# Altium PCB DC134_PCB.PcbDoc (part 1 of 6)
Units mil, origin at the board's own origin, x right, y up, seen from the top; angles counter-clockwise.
Board outline 4000 x 2750 mil, 6 copper layers (L1_Top Layer, L2_GND1, L3_Signal, L4_Plane, L5_GND2, L6_Bottom Layer), stack 60.4 mil thick; 404 components, 244 nets, 1547 pads, 694 vias.
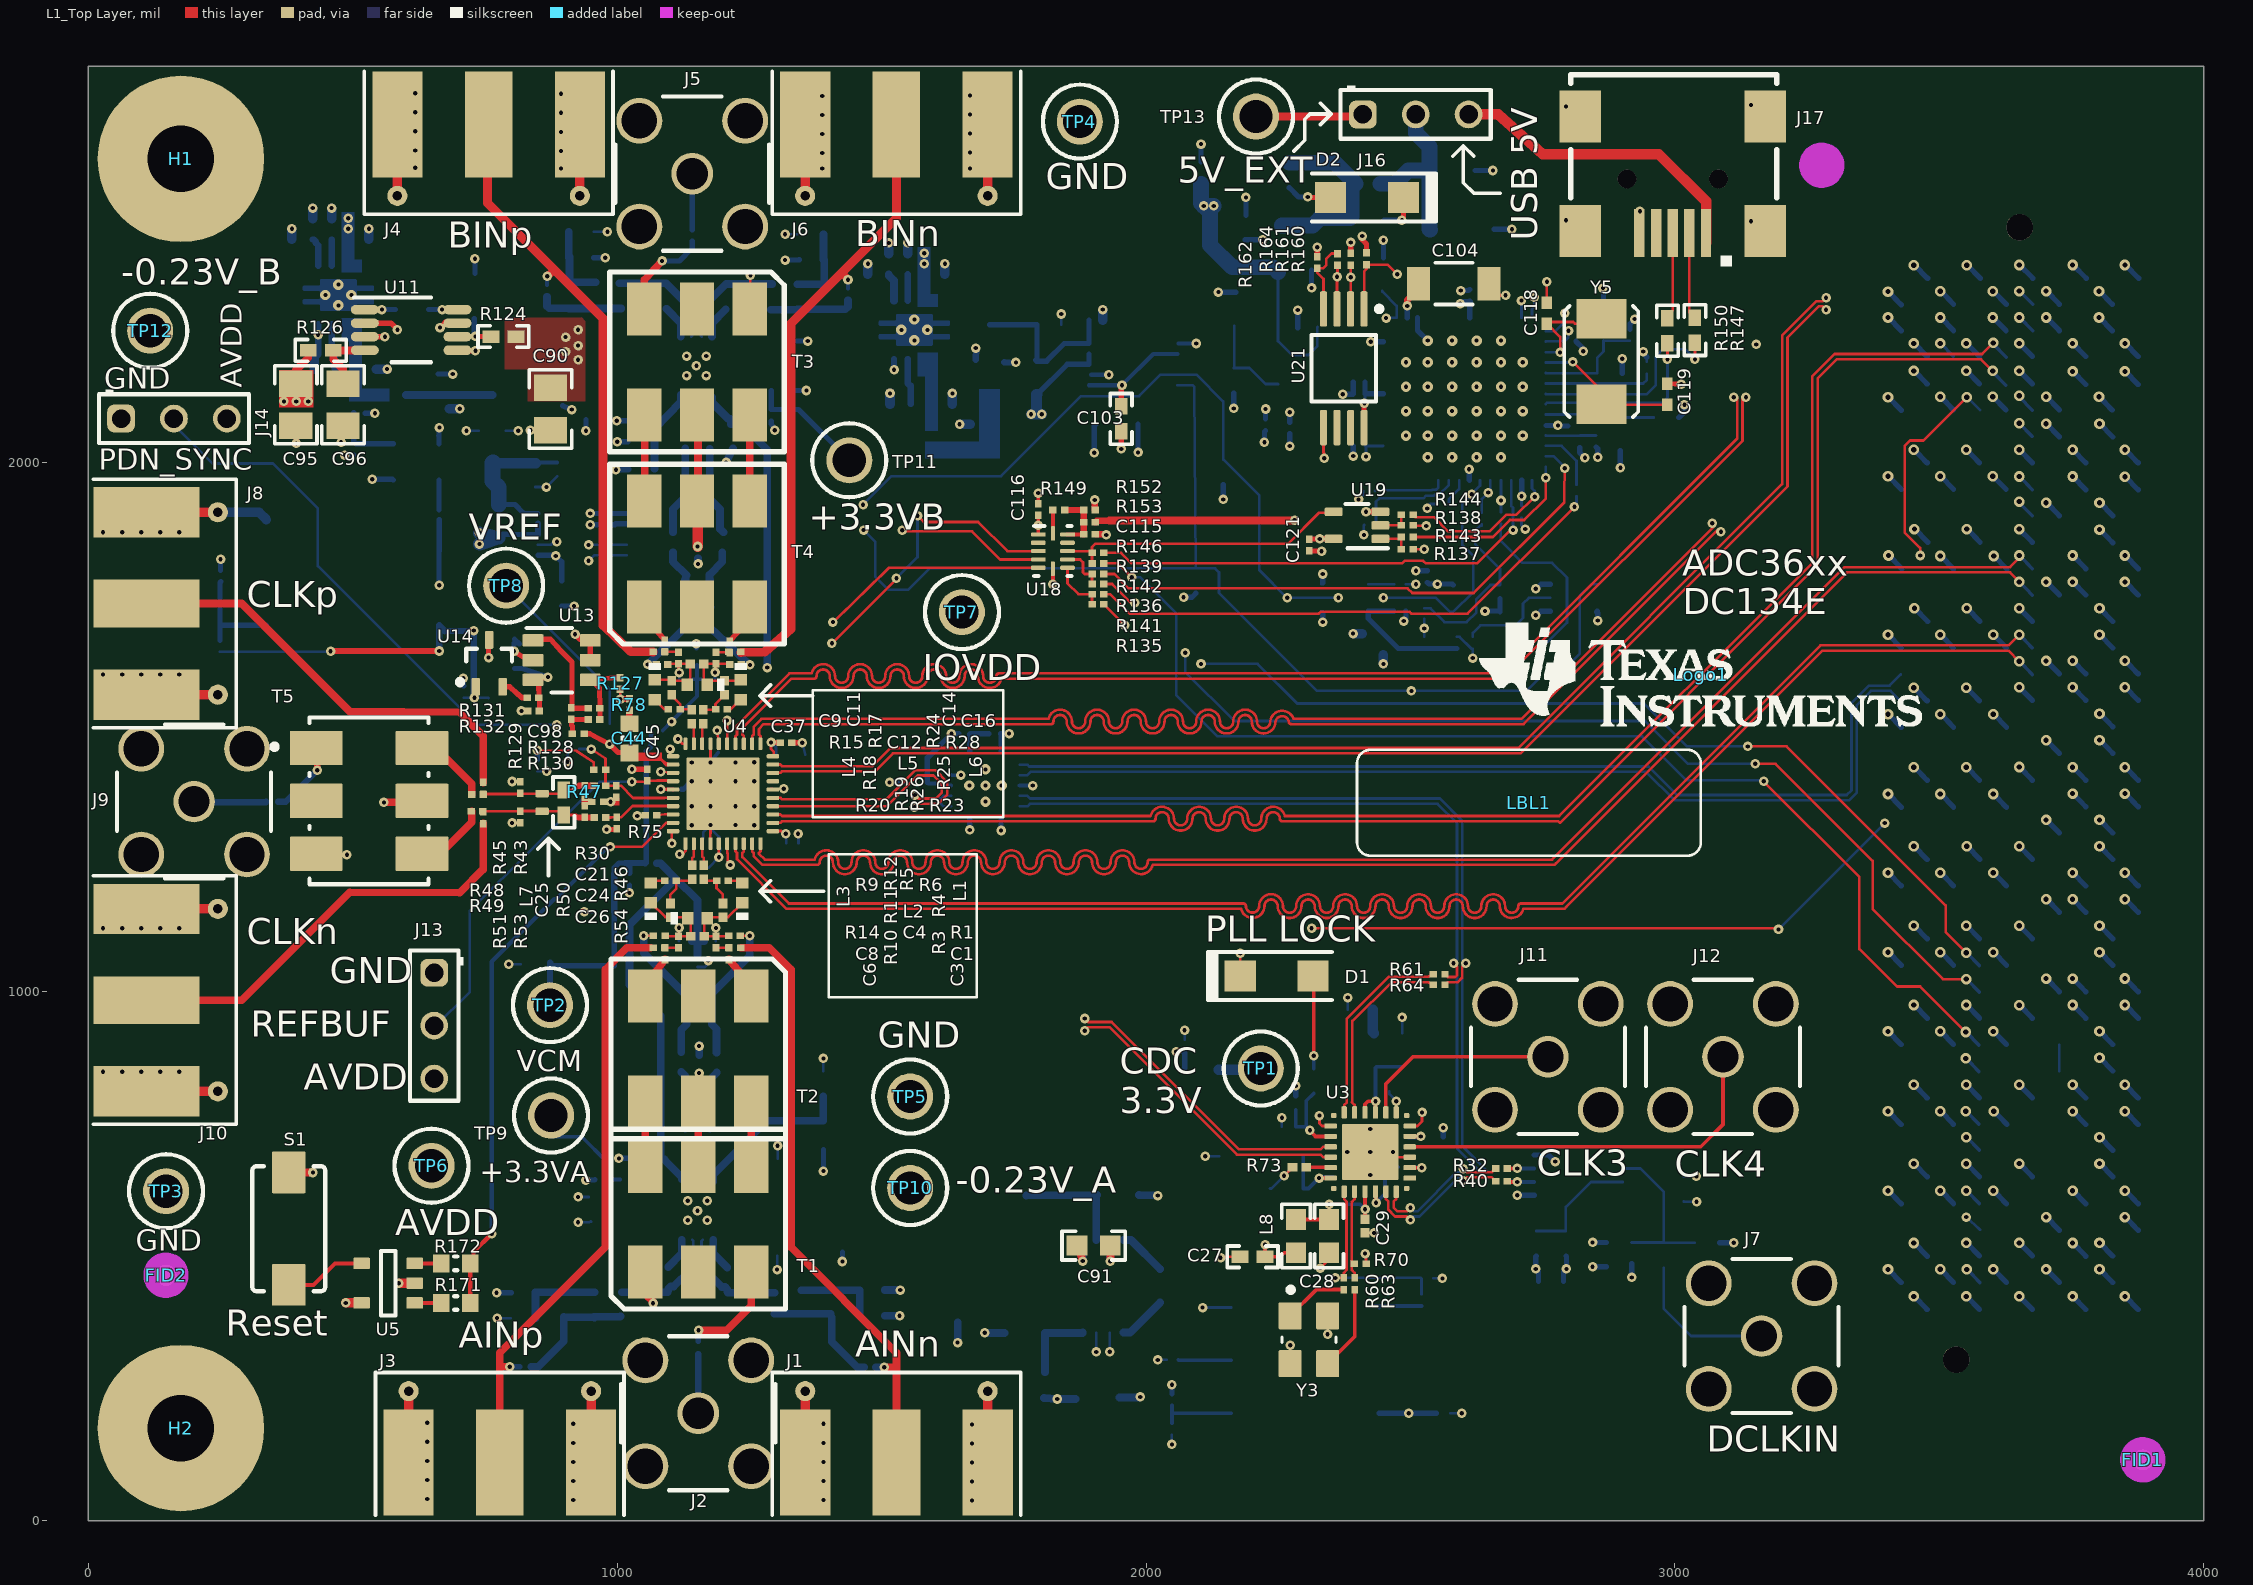
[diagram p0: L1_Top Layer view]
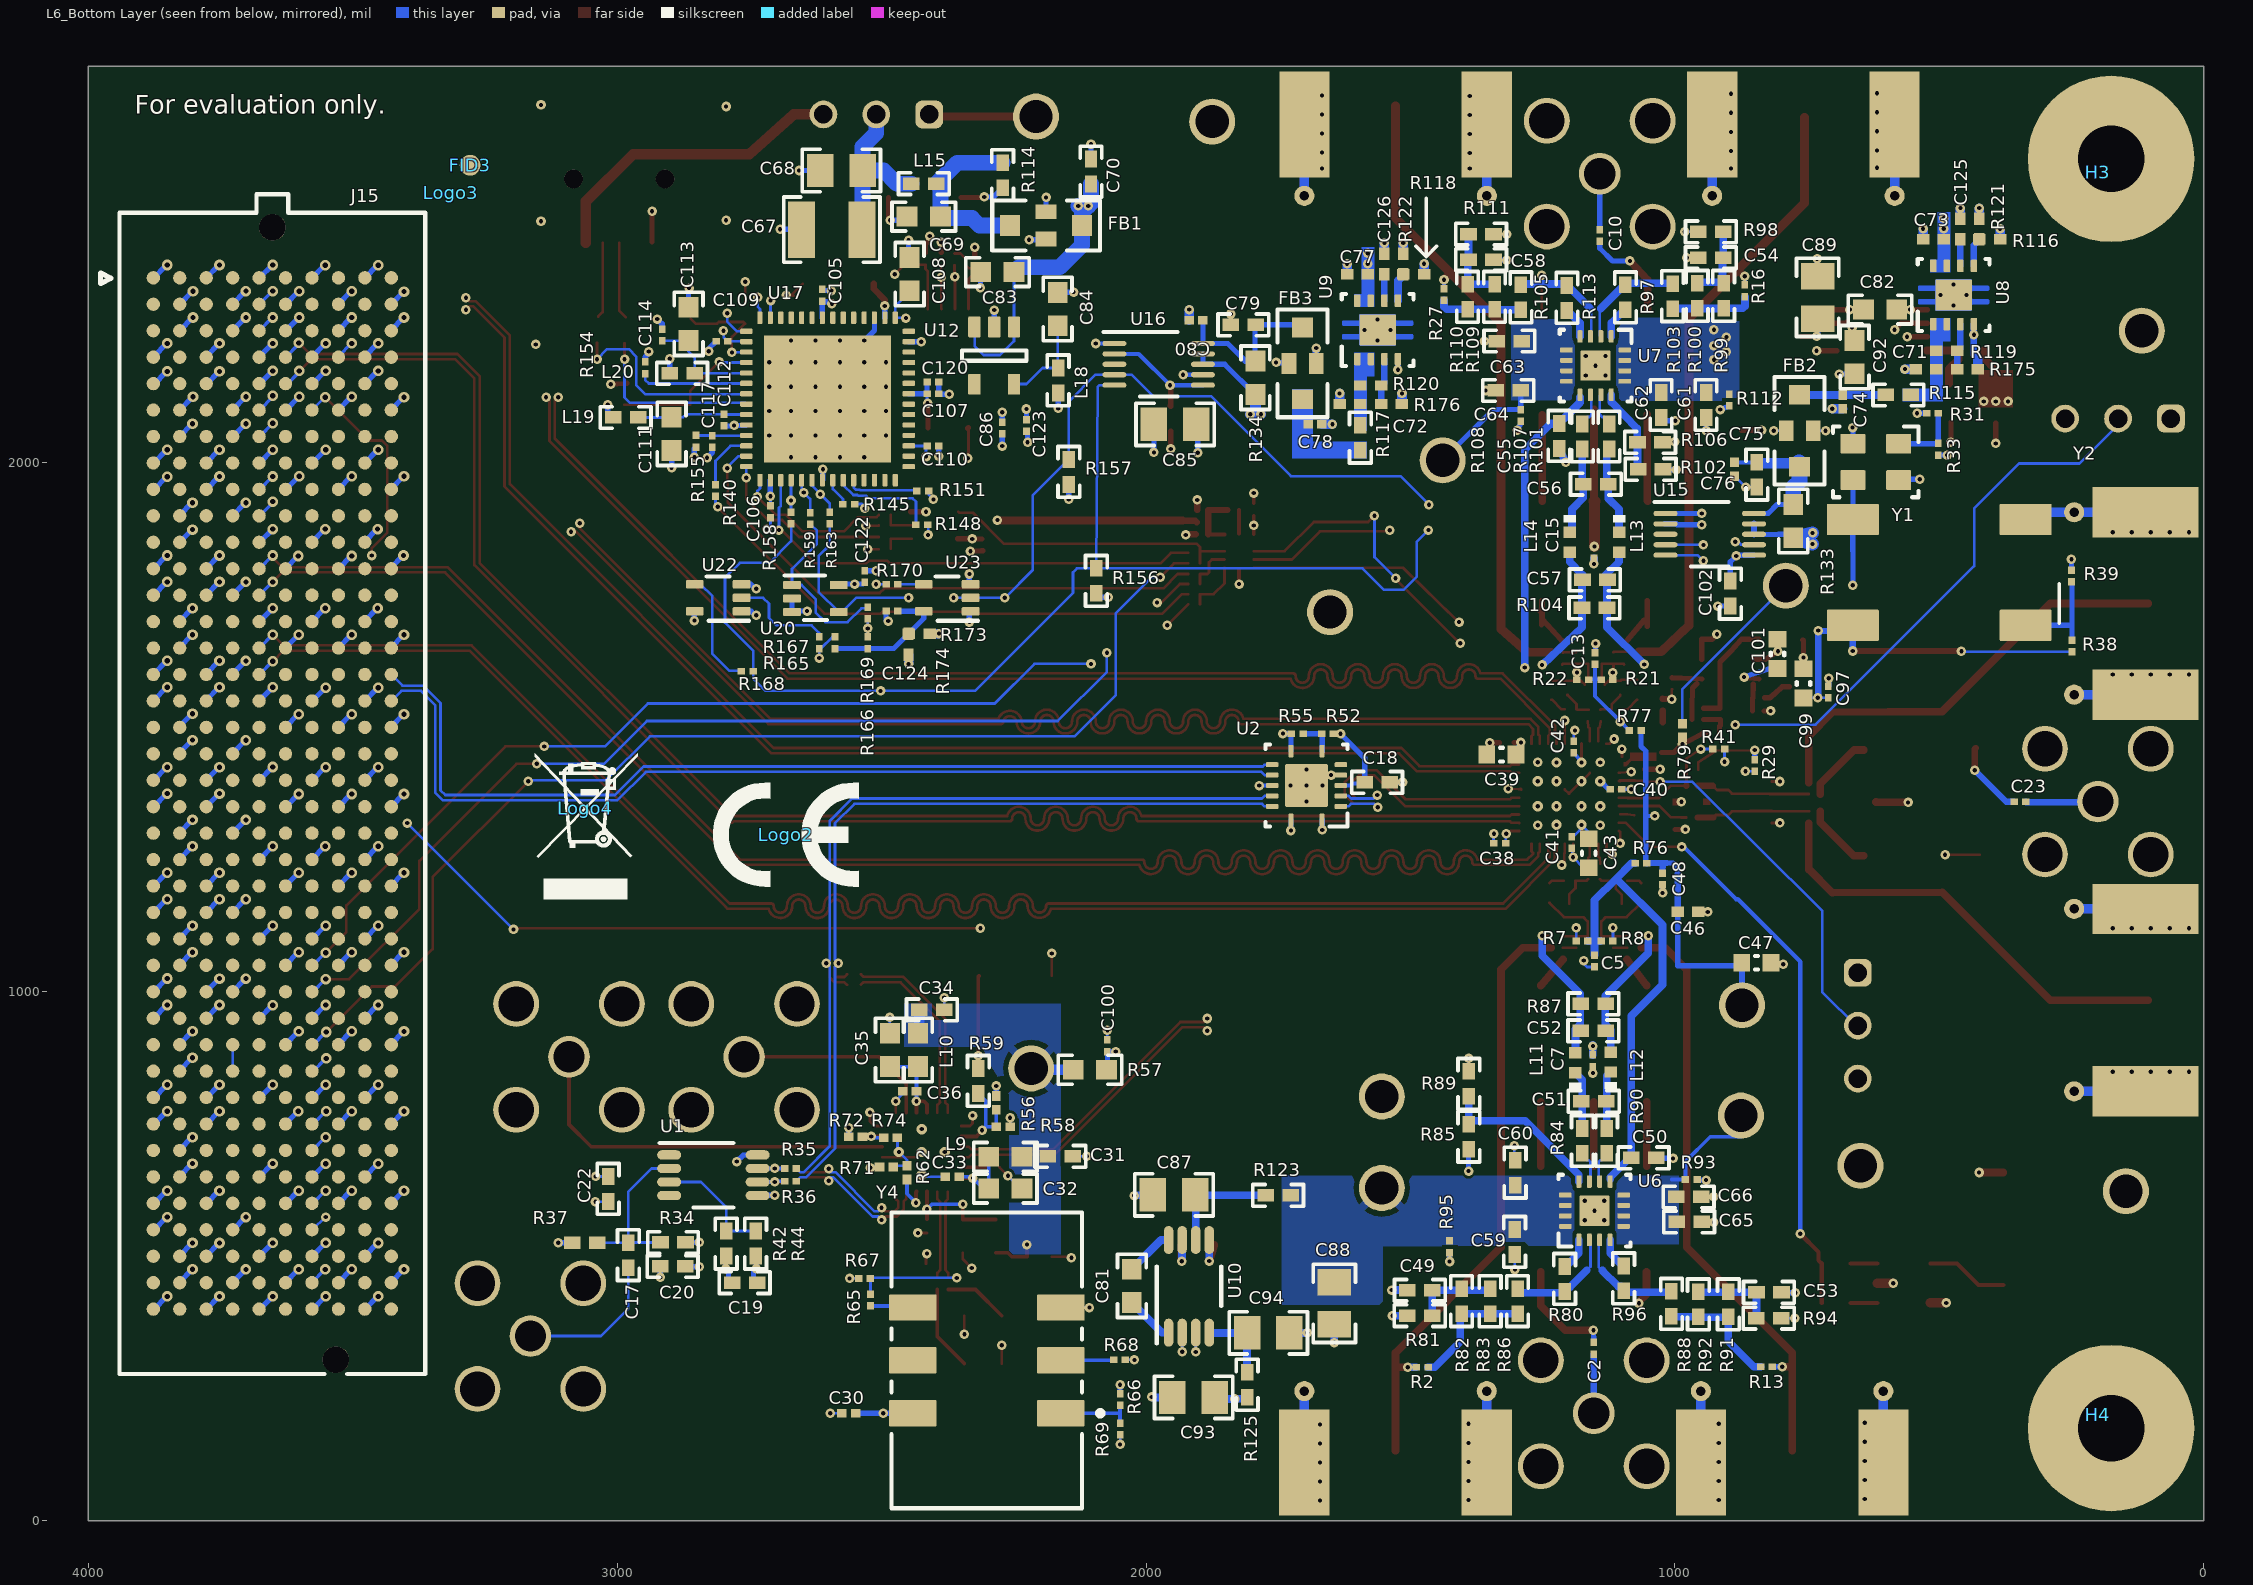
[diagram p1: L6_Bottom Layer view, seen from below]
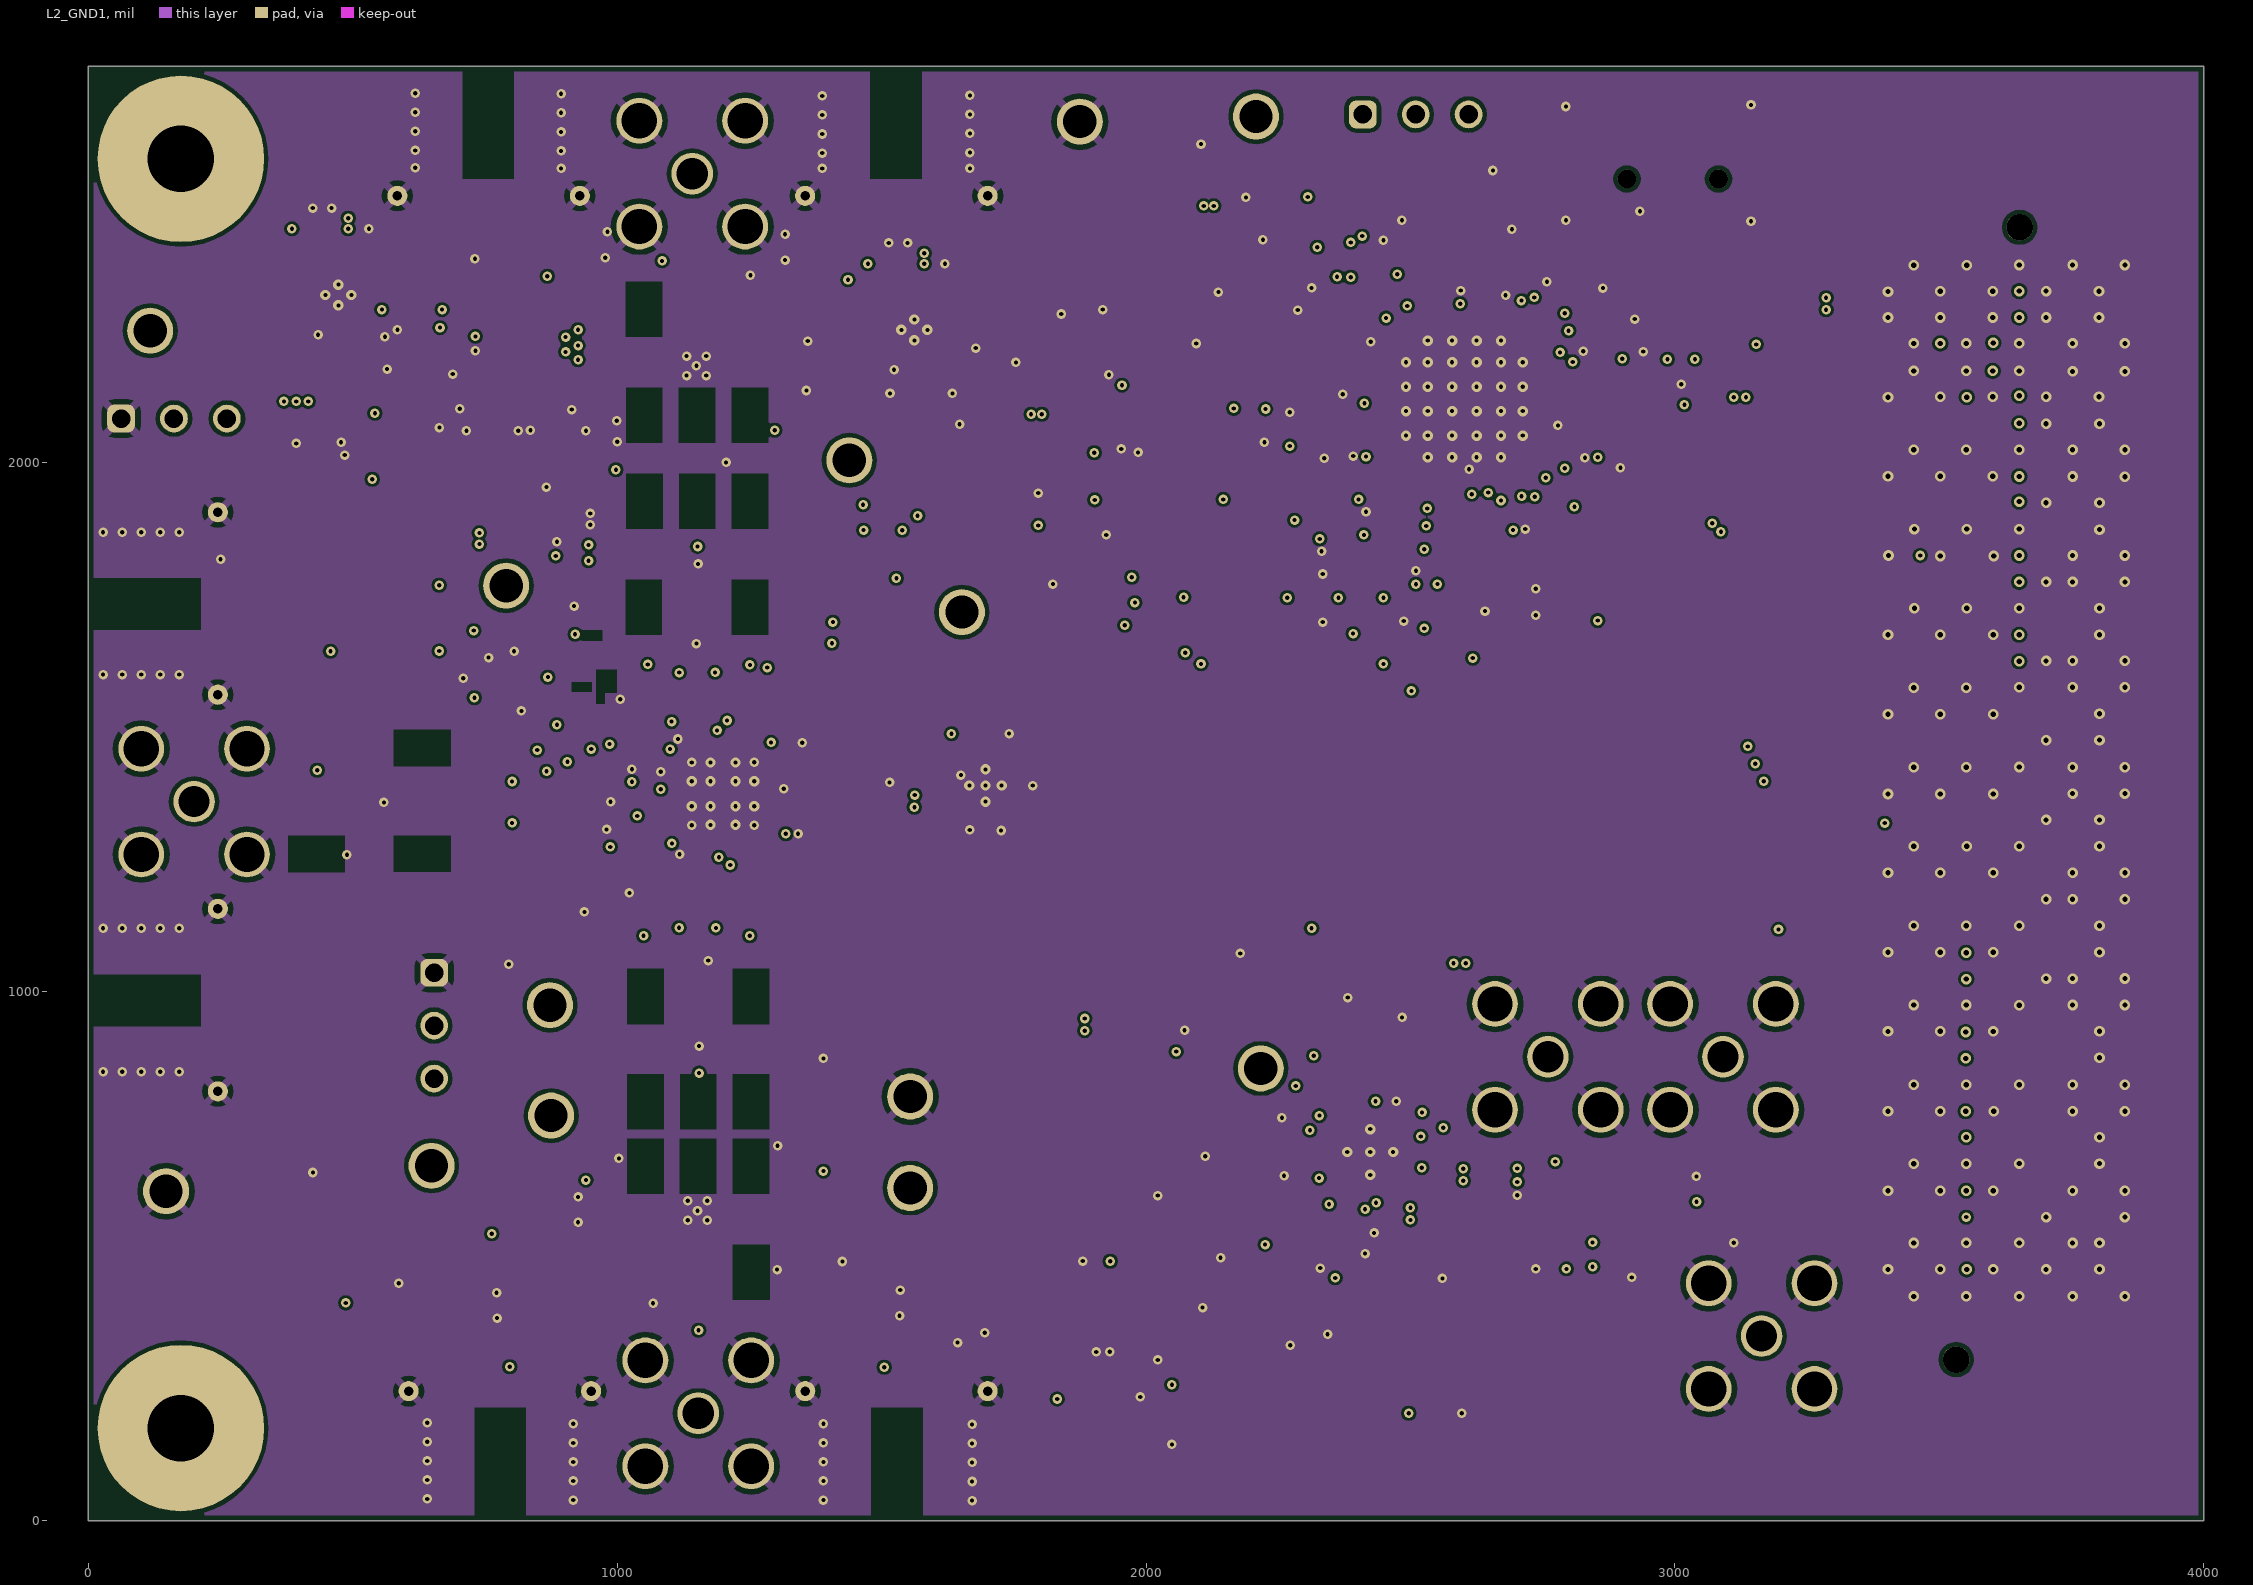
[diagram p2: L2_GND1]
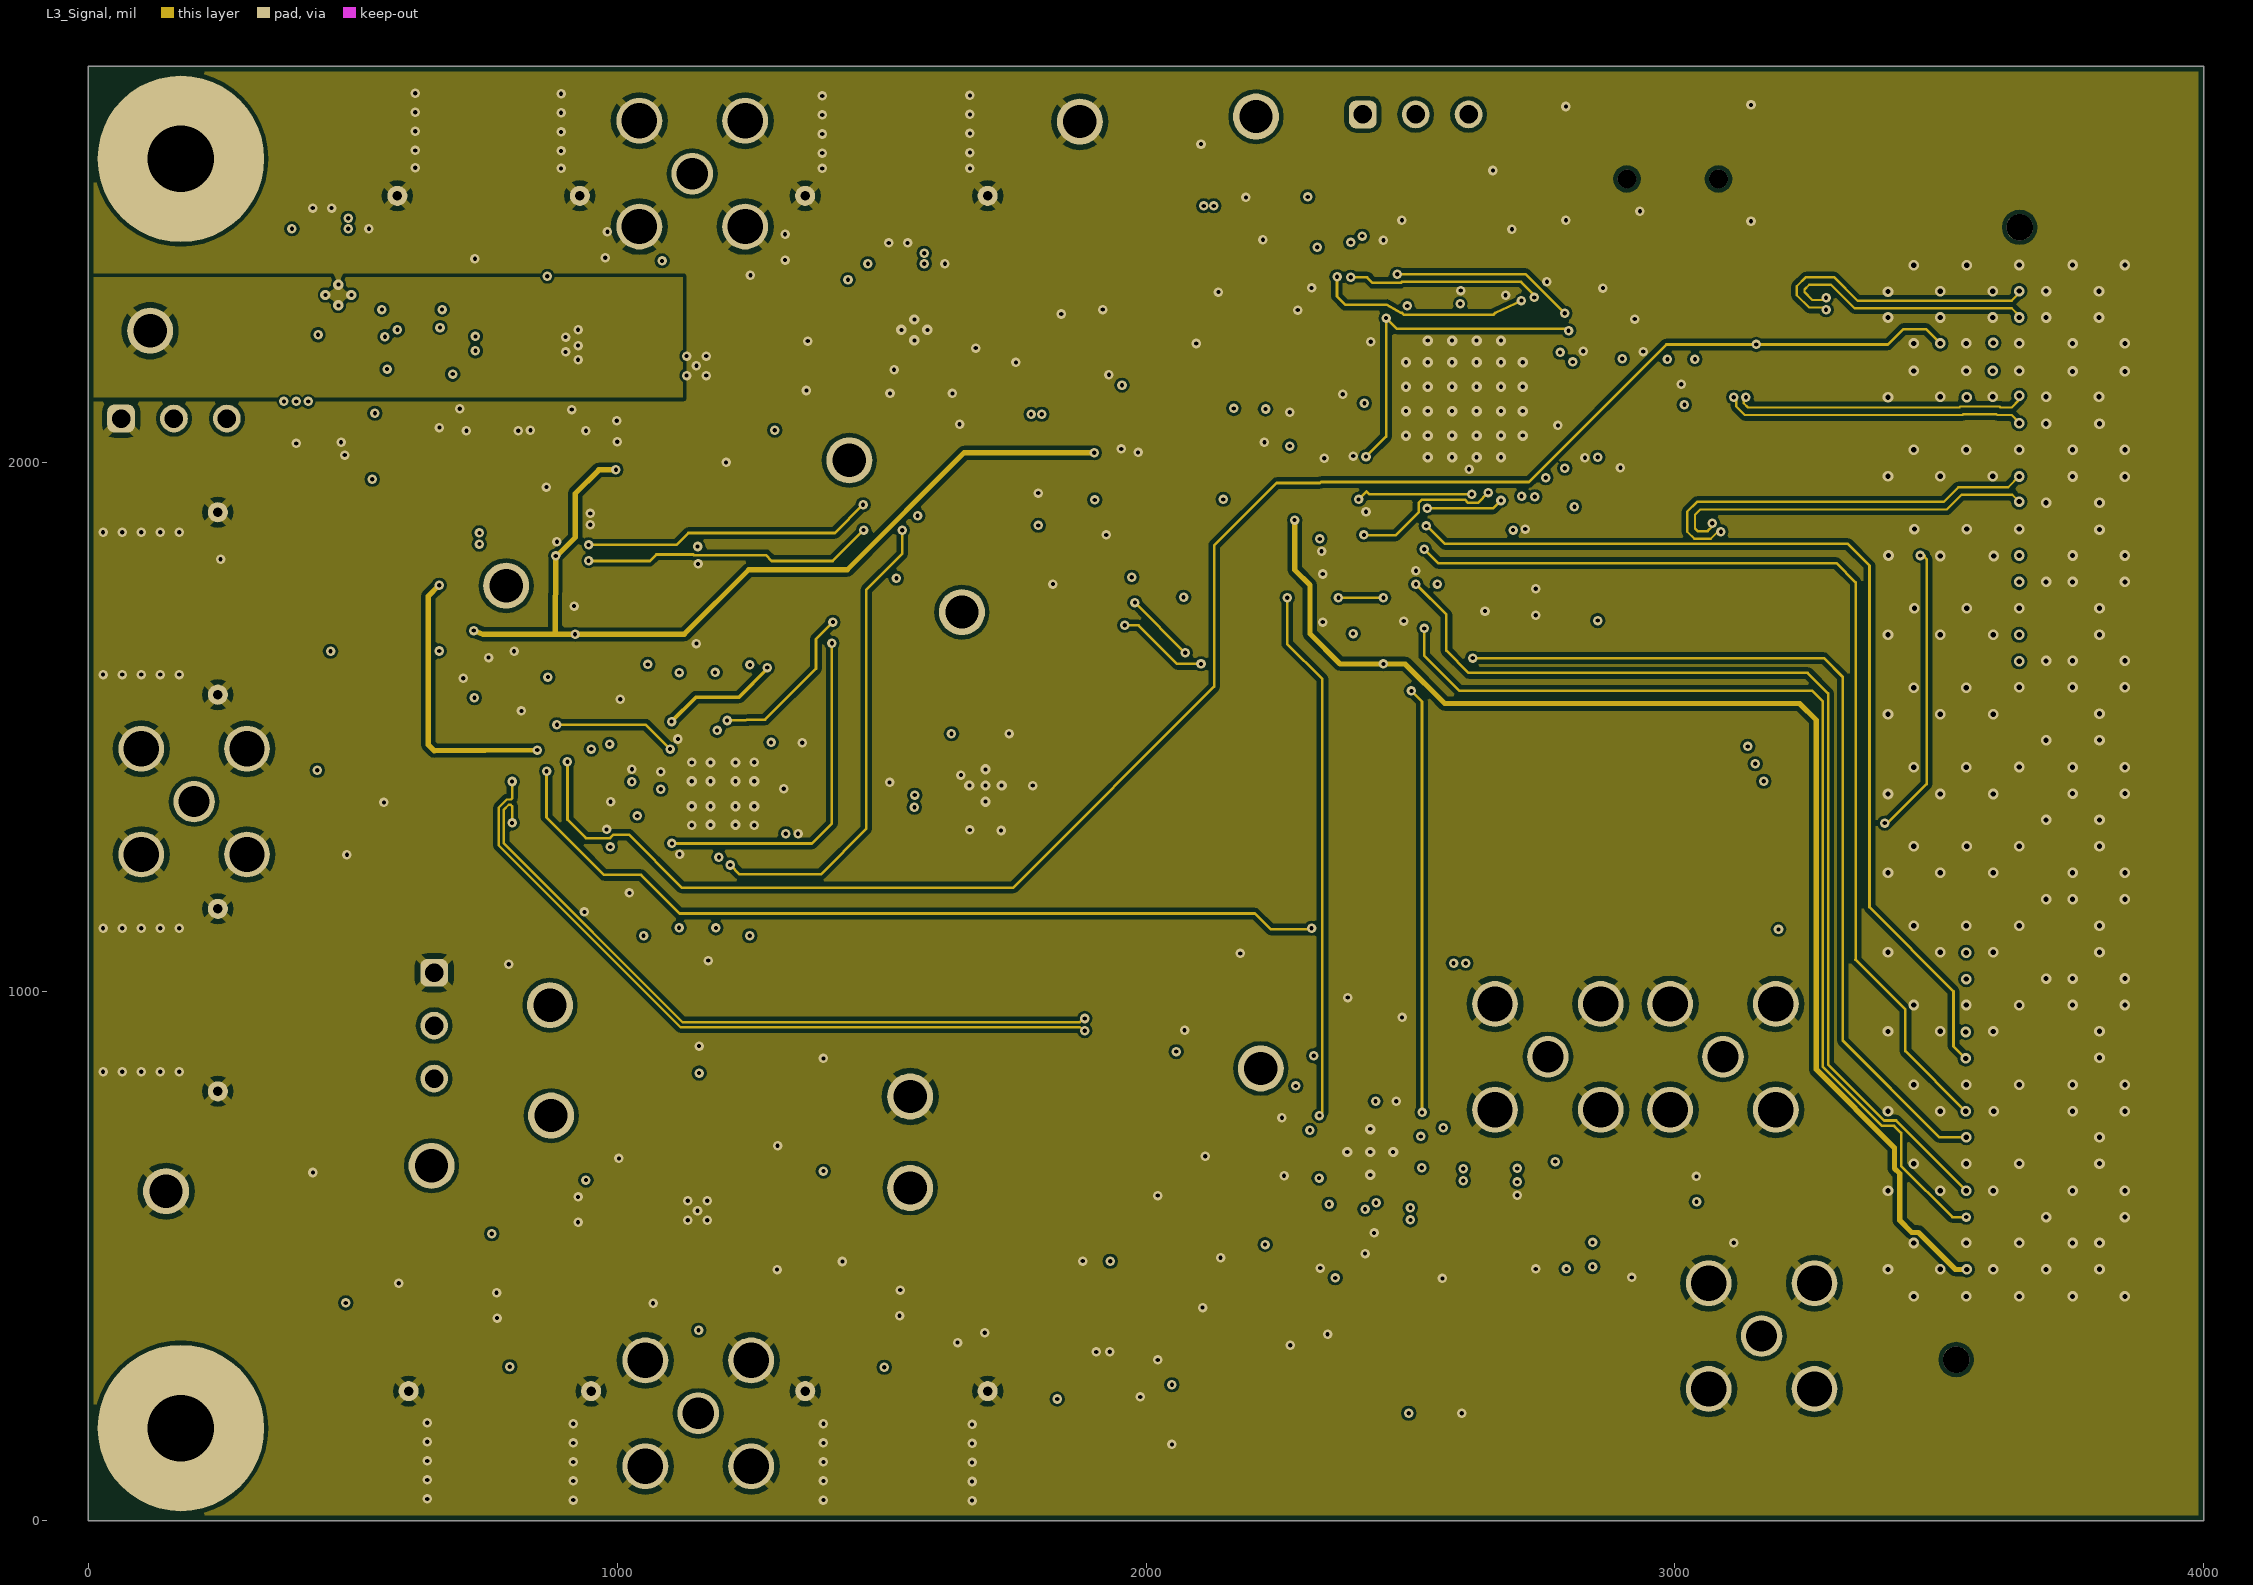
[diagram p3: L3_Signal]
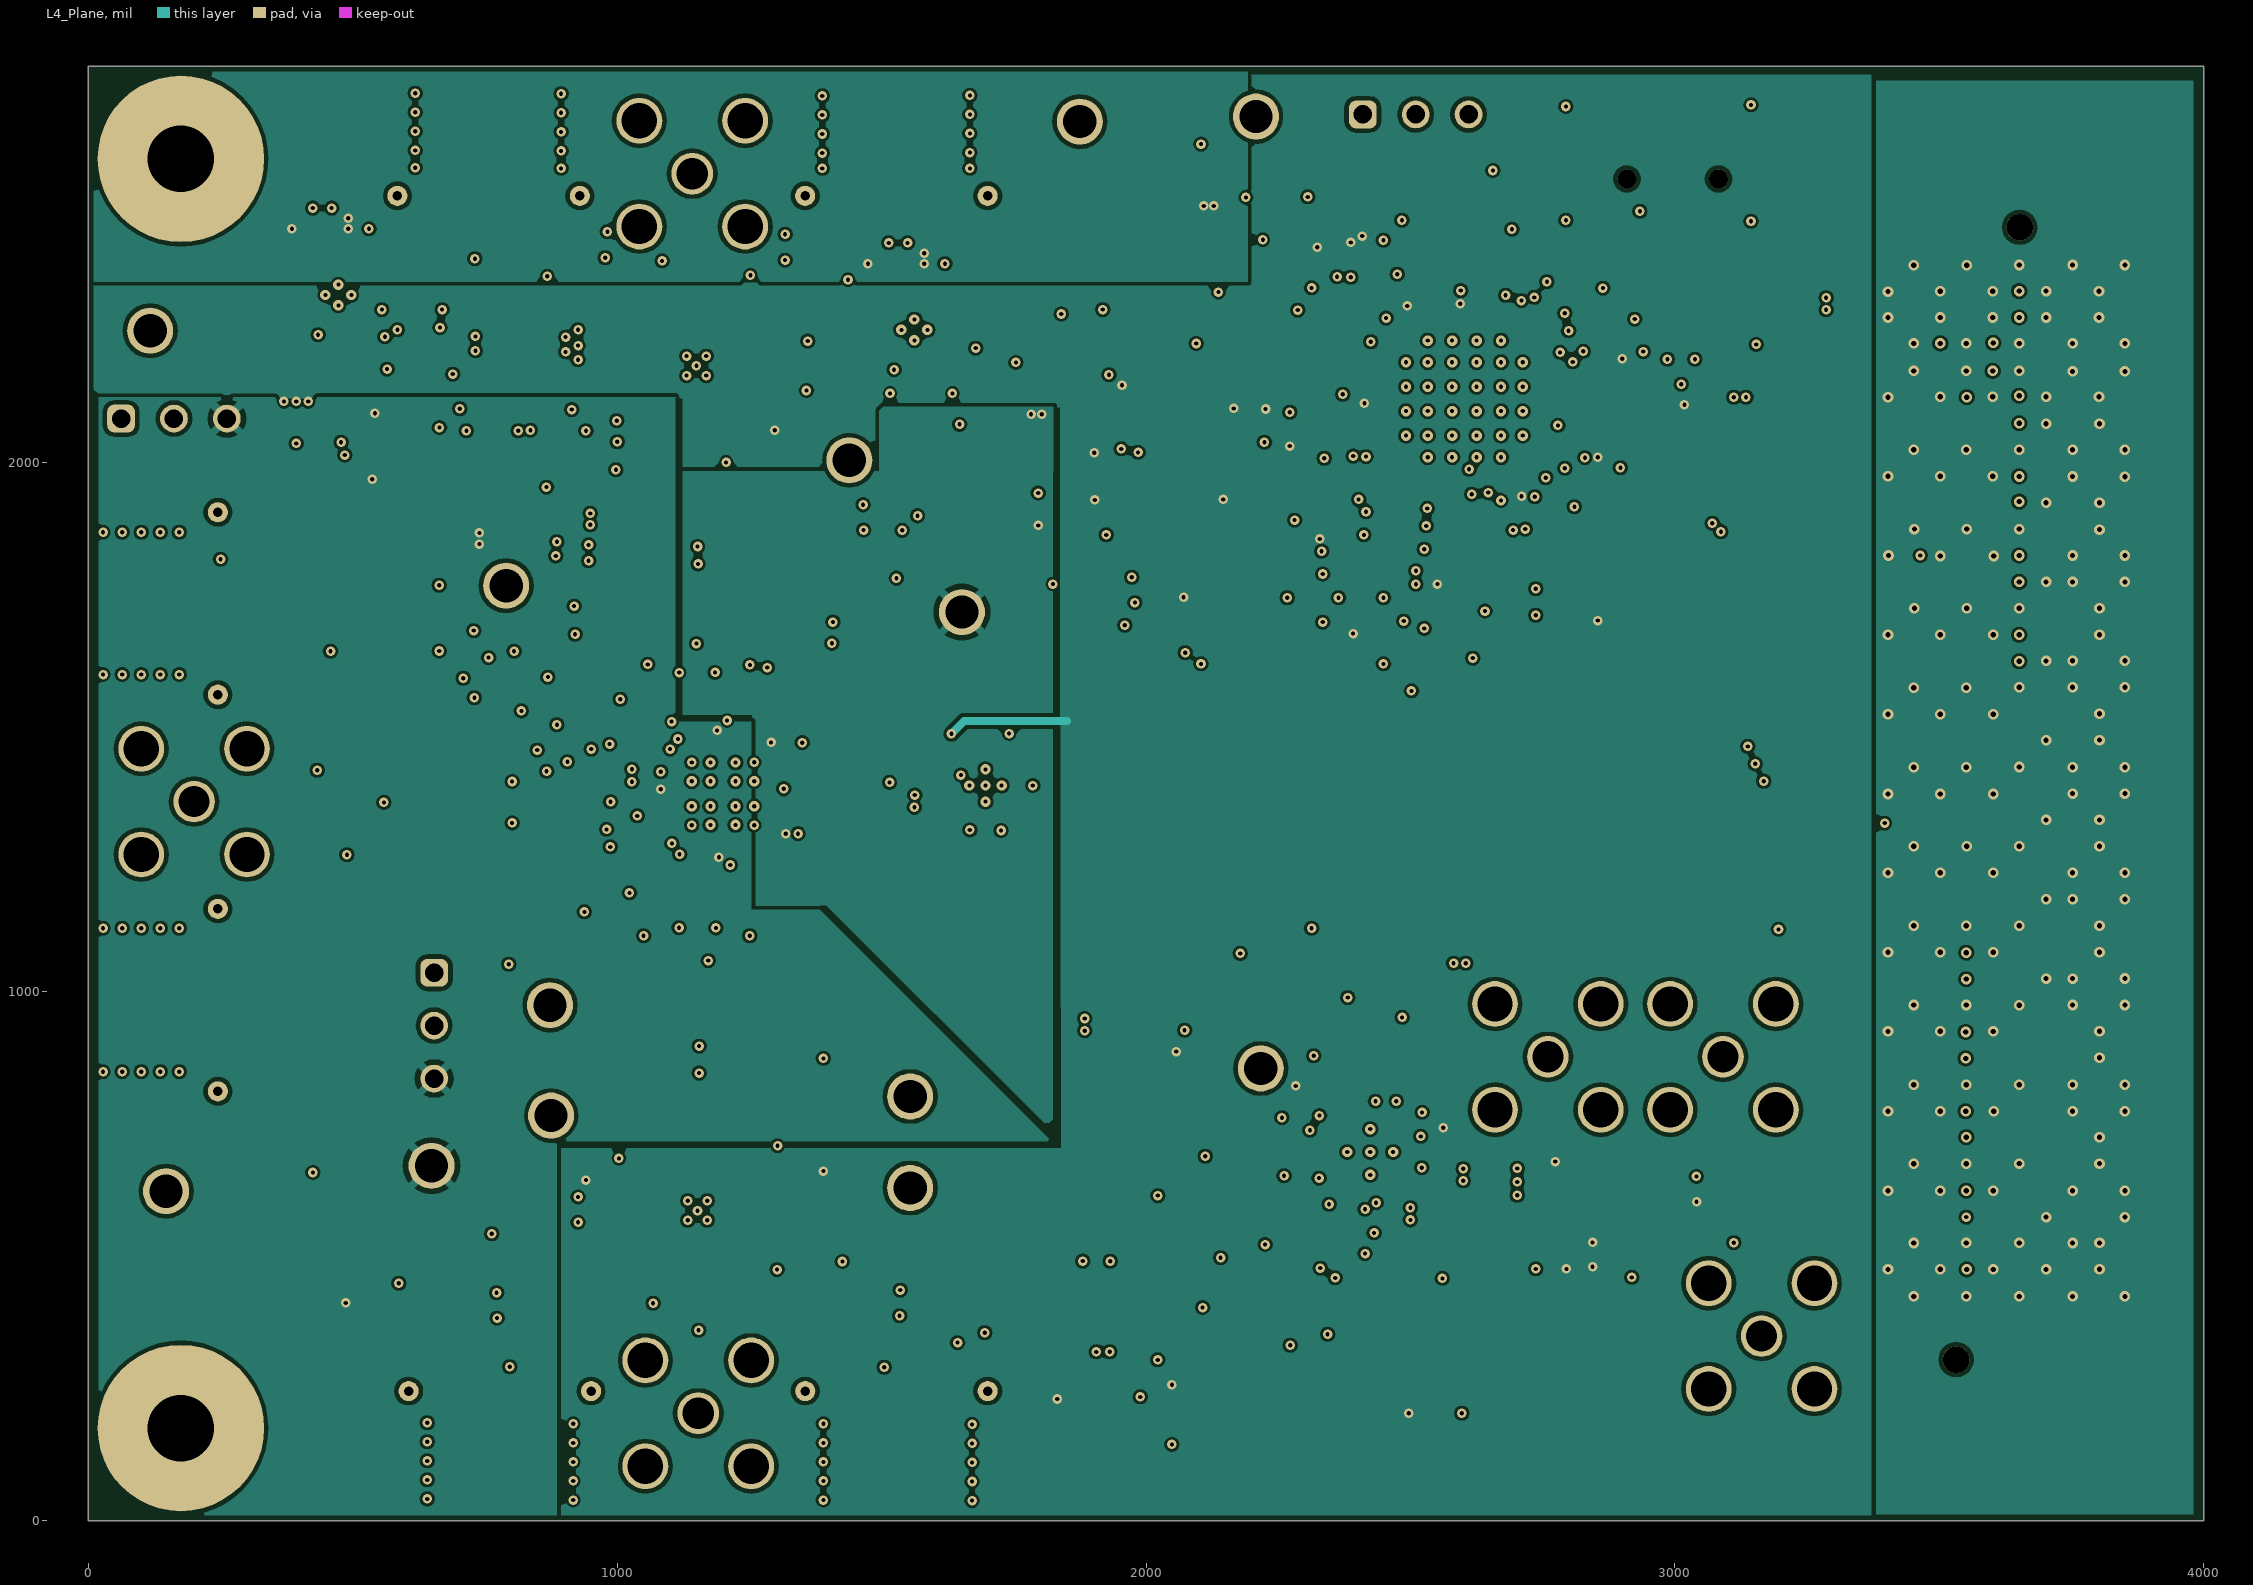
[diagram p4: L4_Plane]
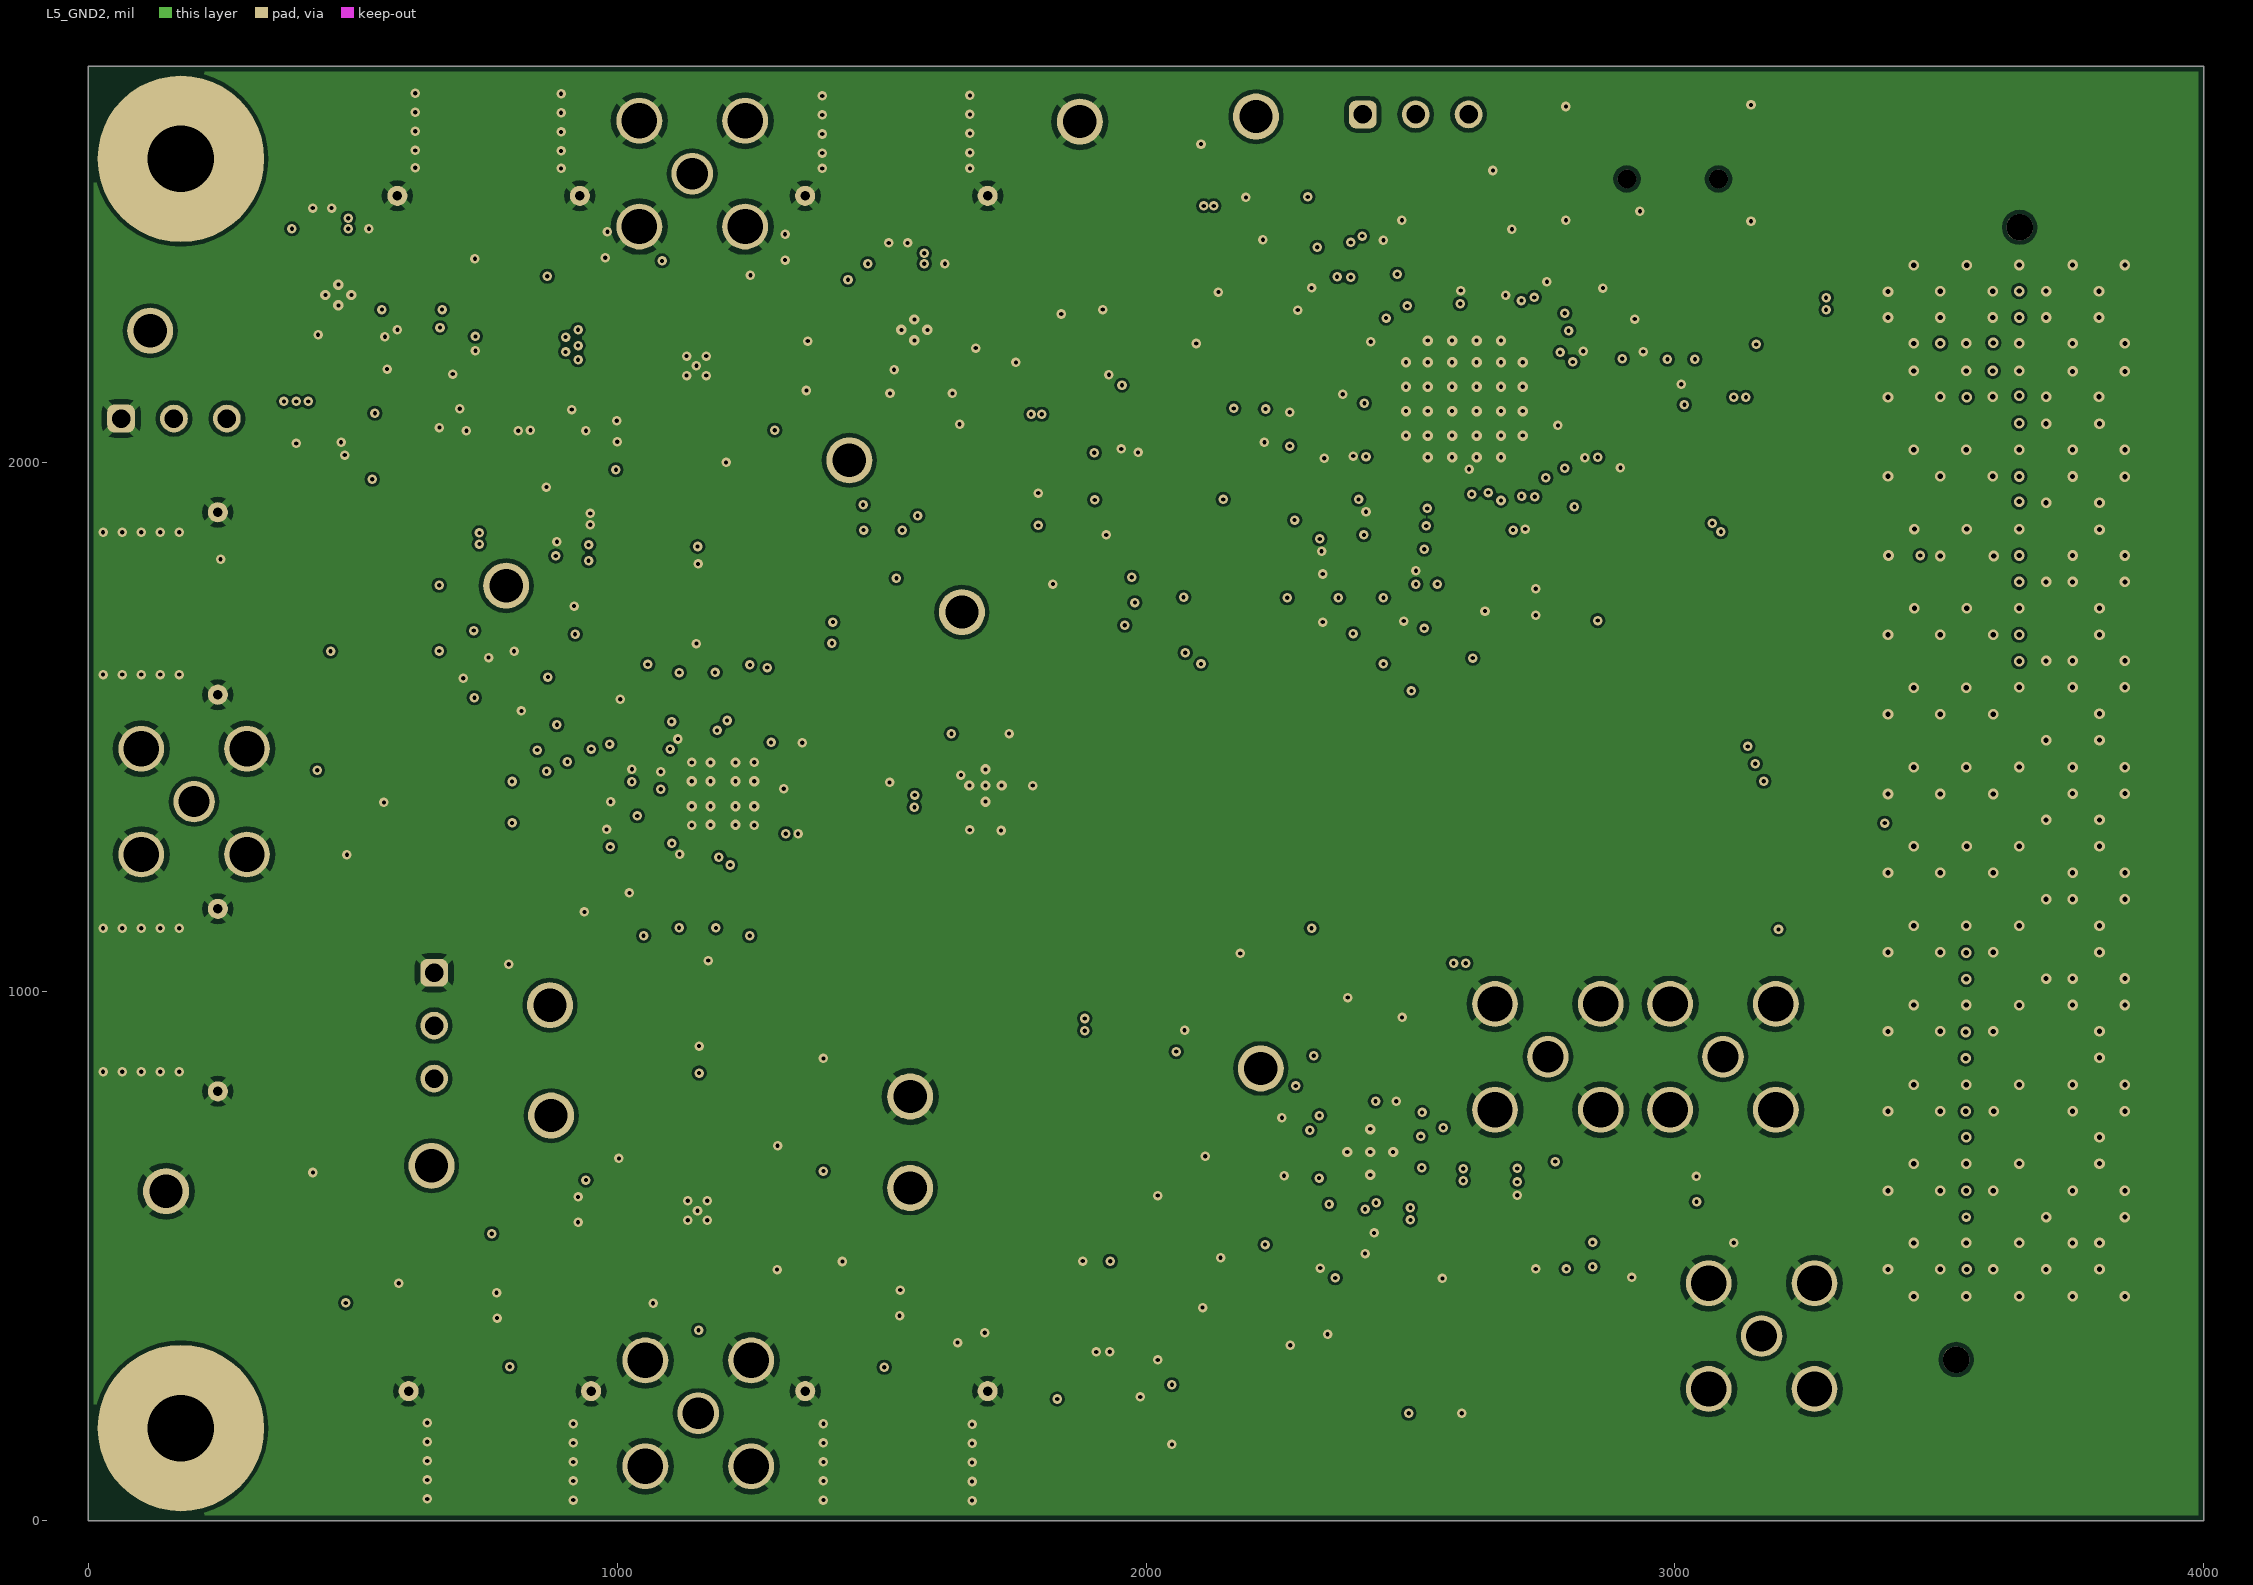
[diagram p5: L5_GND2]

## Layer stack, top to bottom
Top Solder: solder mask 0.5, Solder Resist, Dk 3.5
L1_Top Layer: signal copper 1.4
Dielectric 1: core 8, FR4-370HR, Dk 4.17
L2_GND1: signal copper 1.4
Dielectric 2: prepreg 14, FR4-370HR, Dk 4.05
L3_Signal: signal copper 1.4
Dielectric 3: core 8, FR4-370HR, Dk 4.17
L4_Plane: signal copper 1.4
Dielectric 4: prepreg 14, FR4-370HR, Dk 4.05
L5_GND2: signal copper 1.4
Dielectric 5: core 8, FR4-370HR, Dk 4.17
L6_Bottom Layer: signal copper 1.4
Bottom Solder: solder mask 0.5, Solder Resist, Dk 3.5

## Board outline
0,0 4000,0 4000,2750 0,2750

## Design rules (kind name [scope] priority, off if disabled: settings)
AcuteAngle [All] p1: minimum=4.50000000000000E+0001 checktracksonly=FALSE
AssemblyTestPointUsage [All] p1: valid=2
BoardOutlineClearance BoardOutlineClearance_MountingHoles [OnCopper and InComponentClass('Mounting Holes')] p1: gap=40 ignorepadtopadclearanceinfootprint=FALSE except(50: Text-OutlineEdge Text-CavityEdge Text-CutoutEdge Text-SplitBarrior Text-SplitContinuation)
BoardOutlineClearance BoardOutlineClearance_Poly [OnCopper and IsPoly or HasFootprint('142-0701-801')] p2: gap=10 ignorepadtopadclearanceinfootprint=FALSE
BoardOutlineClearance BoardOutlineClearance_sma [HasFootprint('Johnson_142-0701-801')] p3: gap=10 ignorepadtopadclearanceinfootprint=FALSE
BoardOutlineClearance [OnCopper and Not InComponentClass('Logo') and not InComponentClass('FiducialMark') and not InPoly] p4: gap=30 ignorepadtopadclearanceinfootprint=FALSE
Clearance ClearanceVia [IsVia] p1: gap=5 ignorepadtopadclearanceinfootprint=TRUE
Clearance Clearance_FMC [WithinRoom('FMC')] p2: gap=5 ignorepadtopadclearanceinfootprint=FALSE except(0: Arc-Hole Track-Hole SMDPad-Hole THPad-Hole Via-Hole Fill-Hole Poly-Hole Region-Hole Text-Hole)
Clearance Clearance_Keepouts [((IsTrack Or IsArc) And Not InPoly) And IsFree and IsKeepOut vs ((IsTrack Or IsArc) And Not InPoly) And IsFree and IsKeepOut] p3: gap=5 ignorepadtopadclearanceinfootprint=FALSE except(0: Arc-Hole Track-Hole SMDPad-Hole THPad-Hole Via-Hole Fill-Hole Poly-Hole Region-Hole)
Clearance Clearance_FiducialMark [IsKeepOut and InComponentClass('FiducialMark') vs IsPad and InComponentClass('FiducialMark')] p4: gap=0 ignorepadtopadclearanceinfootprint=FALSE
Clearance ClearancePlane [InPoly] p5: gap=8 ignorepadtopadclearanceinfootprint=TRUE
Clearance [All] p6: gap=5 ignorepadtopadclearanceinfootprint=TRUE
ComponentClearance "ComponentClearance_Pad Share" [InComponent('R1', 'R4', 'C30', 'C7', 'R13') vs InComponent('R7', 'R59', 'C32', 'C22', 'R82')] p1: gap=0 collisioncheckmode=3 verticalgap=0 showdistances=FALSE
ComponentClearance ComponentClearance_MountingHoles_FiducialMarks [InComponentClass('Mounting Holes') vs InComponentClass('FiducialMark')] p2: gap=10 collisioncheckmode=3 verticalgap=10 showdistances=FALSE
ComponentClearance ComponentClearance_Shunt [InComponentClass('Header') vs InComponentClass('Shunt')] p3: gap=0 collisioncheckmode=3 verticalgap=0 showdistances=FALSE
ComponentClearance ComponentClearance_Logo [InComponentClass('Logo')] p4: gap=50 collisioncheckmode=3 verticalgap=10 showdistances=FALSE
ComponentClearance ComponentClearance_ScrewToNut [(HasFootprint('NY PMS 440 0025 PH')) vs (HasFootprint('Keystone_1902C'))] p5: gap=5 collisioncheckmode=3 verticalgap=10 showdistances=FALSE
ComponentClearance ComponentClearance_MountingHoles [InComponentClass('Mounting Holes')] p6: gap=10 collisioncheckmode=3 verticalgap=100000 showdistances=FALSE
ComponentClearance ComponentClearance_SmallPassives [HasFootprint('0201*') or HasFootprint('0402*') or HasFootprint('0508') or HasFootprint('0603*') or HasFootprint('0612') or HasFootprint('0805*') or HasFootprint('0815*') or HasFootprint('0830*') or HasFootprint('1206*') or HasFootprint('1210*') or HasFootprint('1808*') or HasFootprint('1812*') or HasFootprint('1825*') or HasFootprint('2010*') or HasFootprint('2220*') or HasFootprint('2225*') or HasFootprint('2512*') or HasFootprint('2728*') or HasFootprint('3518*') or HasFootprint('LQG15WZ_02') vs HasFootprint('0201*') or HasFootprint('0402*') or HasFootprint('0508') or HasFootprint('0603*') or HasFootprint('0612') or HasFootprint('0805*') or HasFootprint('0815*') or HasFootprint('0830*') or HasFootprint('1206*') or HasFootprint('1210*') or HasFootprint('1808*') or HasFootprint('1812*') or HasFootprint('1825*') or HasFootprint('2010*') or HasFootprint('2220*') or HasFootprint('2225*') or HasFootprint('2512*') or HasFootprint('2728*') or HasFootprint('3518*') or HasFootprint('LQG15WZ_02')] p7: gap=5 collisioncheckmode=3 verticalgap=10 showdistances=FALSE
ComponentClearance ComponentClearance_THtoSMT [IsThruComponent vs IsSMTComponent] p8: gap=5 collisioncheckmode=3 verticalgap=30 showdistances=FALSE
ComponentClearance ComponentClearance_THtoTH [IsThruComponent vs IsThruComponent] p9: gap=5 collisioncheckmode=3 verticalgap=30 showdistances=FALSE
ComponentClearance [All] p10: gap=5 collisioncheckmode=3 verticalgap=10 showdistances=FALSE
DiffPairsRouting DiffPairsRouting_2 [InDifferentialPairClass('OutputFMCPairs')] p1: maxlimit=10 minlimit=4.75 mostfreqgap=5 toplayer_mingap=5 toplayer_maxgap=5 toplayer_minwidth=5 toplayer_maxwidth=5 toplayer_prefwidth=5 midlayer5_mingap=5 midlayer5_maxgap=5 midlayer5_minwidth=4.4 midlayer5_maxwidth=4.4 midlayer5_prefwidth=4.4 midlayer6_maxgap=4.75 midlayer6_prefgap=4.75 midlayer6_minwidth=4.4 midlayer6_maxwidth=4.4 midlayer6_prefwidth=4.4 midlayer7_mingap=10 midlayer7_prefgap=10 midlayer7_minwidth=15 midlayer7_maxwidth=15 midlayer7_prefwidth=15 midlayer8_mingap=10 midlayer8_prefgap=10 midlayer8_minwidth=15 midlayer8_maxwidth=15 midlayer8_prefwidth=15 bottomlayer_mingap=5 bottomlayer_maxgap=5 bottomlayer_minwidth=5 bottomlayer_maxwidth=5 bottomlayer_prefwidth=5 maxuncoupledlength=500
DiffPairsRouting DiffPairs1 [All] p2: maxlimit=10 minlimit=4.75 mostfreqgap=5 toplayer_mingap=5 toplayer_maxgap=5 toplayer_minwidth=5 toplayer_maxwidth=5 toplayer_prefwidth=5 midlayer5_prefgap=10 midlayer5_minwidth=4.4 midlayer5_maxwidth=4.4 midlayer5_prefwidth=4.4 midlayer6_maxgap=4.75 midlayer6_prefgap=4.75 midlayer6_minwidth=4.4 midlayer6_maxwidth=4.4 midlayer6_prefwidth=4.4 midlayer7_mingap=5 midlayer7_maxgap=5 midlayer7_minwidth=5 midlayer7_maxwidth=5 midlayer7_prefwidth=5 midlayer8_mingap=5 midlayer8_maxgap=5 midlayer8_minwidth=5 midlayer8_maxwidth=5 midlayer8_prefwidth=5 bottomlayer_mingap=5 bottomlayer_maxgap=5 bottomlayer_minwidth=5 bottomlayer_maxwidth=5 bottomlayer_prefwidth=5 maxuncoupledlength=500
DiffPairsRouting DiffPair_DIFF90DiffPairsRouting [InDifferentialPairClass('DIFF90')] p3: maxlimit=12 minlimit=10 mostfreqgap=10 toplayer_mingap=12 toplayer_prefgap=12 toplayer_minwidth=12 toplayer_maxwidth=12 toplayer_prefwidth=12 midlayer5_maxgap=10 midlayer5_minwidth=15 midlayer5_maxwidth=15 midlayer5_prefwidth=15 midlayer6_maxgap=10 midlayer6_minwidth=15 midlayer6_maxwidth=15 midlayer6_prefwidth=15 midlayer7_maxgap=10 midlayer7_minwidth=15 midlayer7_maxwidth=15 midlayer7_prefwidth=15 midlayer8_maxgap=10 midlayer8_minwidth=15 midlayer8_maxwidth=15 midlayer8_prefwidth=15 bottomlayer_mingap=12 bottomlayer_prefgap=12 bottomlayer_minwidth=12 bottomlayer_maxwidth=12 bottomlayer_prefwidth=12 maxuncoupledlength=500
DiffPairsRouting [All] p4: maxlimit=100 minlimit=5 mostfreqgap=10 toplayer_maxgap=5 toplayer_prefgap=5 toplayer_minwidth=5 toplayer_maxwidth=5 toplayer_prefwidth=5 midlayer5_mingap=10 midlayer5_minwidth=15 midlayer5_maxwidth=15 midlayer5_prefwidth=15 midlayer6_mingap=10 midlayer6_minwidth=15 midlayer6_maxwidth=15 midlayer6_prefwidth=15 midlayer7_mingap=10 midlayer7_minwidth=15 midlayer7_maxwidth=15 midlayer7_prefwidth=15 midlayer8_mingap=10 midlayer8_minwidth=15 midlayer8_maxwidth=15 midlayer8_prefwidth=15 bottomlayer_maxgap=5 bottomlayer_prefgap=5 bottomlayer_minwidth=5 bottomlayer_maxwidth=5 bottomlayer_prefwidth=5 maxuncoupledlength=1000
FabricationTestPointUsage TestPointUsage [All] p1: valid=2 allowmultiple=FALSE
FabricationTestpoint Testpoint [All] p1: side=3 testpointundercomponent=TRUE minsize=40 maxsize=100 preferedsize=60 minholesize=0 maxholesize=40 preferedholesize=32 testpointgrid=1 allowsidetop=TRUE allowsidebottom=TRUE usegrid=TRUE gridtolerance=0.01
FanoutControl Fanout_LCC [IsLCC] p1: bgadir=Out bgaviamode=Centered fanoutstyle=Auto fanoutdirection=Alternating viagrid=1 // Fanout_LCC (Default Rule)
FanoutControl Fanout_BGA [IsBGA or WithinRoom('FMC')] p2: bgadir=Out bgaviamode=Centered fanoutstyle=BGA fanoutdirection=Alternating viagrid=1 // Fanout_BGA (Default Rule)
FanoutControl Fanout_Default [All] p4: bgadir=Out bgaviamode=Centered fanoutstyle=Auto fanoutdirection=Alternating viagrid=1 // Fanout_Default (Default Rule)
FanoutControl Fanout_Small [(CompPinCount < 5)] p5: bgadir=Out bgaviamode=Centered fanoutstyle=Auto fanoutdirection=OutThenIn viagrid=1 // Fanout_Small (Default Rule)
HoleSize [All] p1: absolutevalues=TRUE maxlimit=251 minlimit=7.87 maxpercent=80.000 minpercent=20.000
MatchedLengths [InNetClass('FMC Connections')] p1: tolerance=10 checknetsindiffpair=FALSE checkdiffpairvsdiffpair=TRUE checkxsignals=TRUE checkothers=TRUE
MatchedLengths SDA_SDIo [InDifferentialPair('DA0') and InDifferentialPair('DA1')] p2: tolerance=5 checknetsindiffpair=FALSE checkdiffpairvsdiffpair=TRUE checkxsignals=TRUE checkothers=TRUE
MatchedLengths Output [InDifferentialPair('DCLKIN_SMA')] p3: tolerance=5 checknetsindiffpair=FALSE checkdiffpairvsdiffpair=TRUE checkxsignals=TRUE checkothers=TRUE
MatchedLengths DiffPair_DIFF100MatchedLengths [InDifferentialPairClass('DIFF100')] p4: tolerance=5 checknetsindiffpair=TRUE checkdiffpairvsdiffpair=FALSE checkxsignals=FALSE checkothers=FALSE
MatchedLengths DiffPair_DIFF90MatchedLengths [InDifferentialPairClass('DIFF90')] p5: tolerance=5 checknetsindiffpair=TRUE checkdiffpairvsdiffpair=FALSE checkxsignals=FALSE checkothers=FALSE
MinimumAnnularRing MinimumAnnularRing_ThermalPadVias [IsVia and InAnyComponent] p1: minimumring=5
MinimumAnnularRing [All] p2: minimumring=5
MinimumSolderMaskSliver MinimumSolderMaskSliver_Logo [InComponentClass('Logo') vs InComponentClass('Logo')] p1: minsoldermaskwidth=0.7
MinimumSolderMaskSliver [All] p2: minsoldermaskwidth=3.74
PlaneClearance [All] p1: clearance=10
PlaneConnect [All] p1: planeconnectstyle=Direct reliefexpansion=5 reliefentries=4 reliefconductorwidth=5 reliefairgap=5
PolygonConnect ViaConnect [All] p1: thpad.connectstyle=Relief thpad.reliefconductorwidth=15 thpad.reliefentries=4 thpad.polygonreliefangle="45 Angle" thpad.airgapwidth=10 smdpad.connectstyle=Direct smdpad.reliefconductorwidth=10 smdpad.reliefentries=4 smdpad.polygonreliefangle="90 Angle" smdpad.airgapwidth=10 via.connectstyle=Direct via.reliefconductorwidth=10 via.reliefentries=4 via.polygonreliefangle="90 Angle" via.airgapwidth=10
RoutingVias RoutingVias_FMC [WithinRoom('FMC')] p1: holewidth=8 width=18 viastyle="Through Hole" minholewidth=8 minwidth=18 maxholewidth=8 maxwidth=18
RoutingVias ThermalPadVias [IsVia and InAnyComponent] p2: holewidth=7.87 width=19.68 viastyle="Through Hole" minholewidth=7.87 minwidth=19.68 maxholewidth=12.99 maxwidth=23.62
RoutingVias [All] p3: holewidth=8 width=18 viastyle="Through Hole" minholewidth=7.87 minwidth=18 maxholewidth=40 maxwidth=65
SilkToBoardRegionClearance [Not ((IsComment or IsDesignator) And (Hide <> 'False')) and not InRegion(1000,500,4000,800)] p1:
SilkToSilkClearance SilkToSilkClearance_Pb-FreeLogo [(HasFootprint('Pb-Free_Overlay_Medium') OR HasFootprint('Pb-Free_Overlay_Small')) vs (HasFootprint('Pb-Free_Overlay_Medium') OR HasFootprint('Pb-Free_Overlay_Small'))] p1: silktosilkclearance=0
SilkToSilkClearance [All] p2: silktosilkclearance=3
SilkToSolderMaskClearance SilkToComponentPadClearance [(IsPad or IsFill or IsRegion) and InAnycomponent] p1: minsilkscreentomaskgap=3.2 clearancetoexposedcopper=TRUE
SilkToSolderMaskClearance "Silk to Solder Mask Opening" [All] p2: minsilkscreentomaskgap=4 clearancetoexposedcopper=FALSE
SolderMaskExpansion [All] p1: expansion=1.97 istentingtop=FALSE
Width Width_FMC [WithinRoom('FMC')] p1: maxlimit=5 minlimit=5 preferedwidth=5
Width [All] p2: maxlimit=100 minlimit=5 preferedwidth=5 checkconnectedcopper=TRUE
14 further rules are at their usual default settings.

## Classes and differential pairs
component class DC134_FDA: C49 C50 C51 C52 C53 C54 C55 C56 C57 C58 C59 C60 C61 C62 C63 C64 C65 C66 L11 L12 L13 L14 R80 R81 R82 R83 R84 R85 R86 R87 R88 R89 R90 R91 R92 R93 R94 R95 R96 R97 R98 R99 R100 R101 R102 R103 R104 R105 R106 R107 R108 R109 R110 R111 R112 R113 TP9 TP10 TP11 TP12 U6 U7
component class Label: LBL1
component class Header: J13 J14 J16
component class DC134_AIN: C1 C2 C3 C4 C5 C6 C7 C8 C9 C10 C11 C12 C13 C14 C15 C16 J1 J2 J3 J4 J5 J6 L1 L2 L3 L4 L5 L6 R1 R2 R3 R4 R5 R6 R7 R8 R9 R10 R11 R12 R13 R14 R15 R16 R17 R18 R19 R20 R21 R22 R23 R24 R25 R26 R27 R28 T1 T2 T3 T4
component class DC134_Power: C67 C68 C69 C70 C71 C72 C73 C74 C75 C76 C77 C78 C79 C80 C81 C82 C83 C84 C85 C86 C87 C88 C89 C90 C91 C92 C93 C94 C95 C96 C125 C126 D2 FB1 FB2 FB3 FB4 J16 J18 L15 L18 L21 R114 R115 R116 R117 R118 R119 R120 R121 R122 R123 R124 R125 R126 R175 R176 TP13 U8 U9 U10 U11 U12
component class DC134_FMC: J15
component class DC134_Device: C37 C38 C39 C40 C41 C42 C43 C44 C45 C46 C47 C48 J13 J14 R75 R76 R77 R78 R79 R171 R172 S1 TP2 TP3 TP4 TP5 TP6 TP7 TP8 U4 U5
component class DC134_CLK: C17 C18 C19 C20 C21 C22 C23 C24 C25 C26 C27 C28 C29 C30 C31 C32 C33 C34 C35 C36 D1 J7 J8 J9 J10 J11 J12 L7 L8 L9 L10 R29 R30 R31 R32 R33 R34 R35 R36 R37 R38 R39 R40 R41 R42 R43 R44 R45 R46 R47 R48 R49 R50 R51 R52 R53 R54 R55 R56 R57 R58 R59 R60 R61 R62 R63 R64 R65 R66 R67 R68 R69 R70 R71 R72 R73 R74 T5 TP1 U1 U2 U3 Y1 Y2 Y3 Y4
component class "Mounting Holes": H1 H2
component class Logo: Logo1
component class DC134_Hardware: FID1 FID2 FID3 H1 H2 H3 H4 LBL1 Logo1 Logo2 Logo3 Logo4 ZZ1 ZZ2 ZZ3
component class FiducialMark: FID1 FID2 FID3
component class AssemblyNote: ZZ1 ZZ2 ZZ3
component class DC134_USB: C104 C105 C106 C107 C108 C109 C110 C111 C112 C113 C114 C115 C116 C117 C118 C119 C120 C121 C122 C123 C124 J17 L19 L20 R135 R136 R137 R138 R139 R140 R141 R142 R143 R144 R145 R146 R147 R148 R149 R150 R151 R152 R153 R154 R155 R156 R157 R158 R159 R160 R161 R162 R163 R164 R165 R166 R167 R168 R169 R170 R173 R174 U17 U18 U19 U20 U21 U22 U23 Y5
component class DC134_Reference: C97 C98 C99 C100 C101 C102 C103 R127 R128 R129 R130 R131 R132 R133 R134 U13 U14 U15 U16
differential pair DCLKIN_CDC: +DCLKIN_CDC_P -DCLKIN_CDC_N
differential pair SECREF: +SECREF_P -SECREF_N
differential pair InternalCLK: +InternalCLK_P -InternalCLK_N
differential pair AMP_CHB_OUT: +AMP_CHB_OUT_P -AMP_CHB_OUT_N
differential pair AMP_CHB_IN: +AMP_CHB_IN_P -AMP_CHB_IN_N
differential pair AMP_CHA_OUT: +AMP_CHA_OUT_P -AMP_CHA_OUT_N
differential pair AMP_CHA_IN: +AMP_CHA_IN_P -AMP_CHA_IN_N
differential pair DCLKIN_SMA: +DCLKIN_SMA_P -DCLKIN_SMA_N
differential pair FCLK: +FCLK_P -FCLK_N
differential pair DCLK: +DCLK_P -DCLK_N
differential pair DCLKIN: +DCLKIN_P -DCLKIN_N
differential pair DCLKIN_FPGA: +DCLKIN_FPGA_P -DCLKIN_FPGA_N
differential pair DB1: +DB1_P -DB1_N
differential pair DB0: +DB0_P -DB0_N
differential pair DA1: +DA1_P -DA1_N
differential pair DA0: +DA0_P -DA0_N
differential pair BIN: +BIN_P -BIN_N
differential pair SMA_CLK: +SMA_CLK_P -SMA_CLK_N
differential pair AIN: +AIN_P -AIN_N
differential pair CLK: +CLK_P -CLK_N

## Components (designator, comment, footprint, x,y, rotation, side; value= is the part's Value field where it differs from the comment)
C1 "GRM033Z71C104KE14D" 0201L 1222.39,1083.02 r180 top value=0.1uF
C2 "GRM033Z71C104KE14D" 0201L 1153.37,326.02 r90 bottom value=0.1uF
C3 "GRM033Z71C104KE14D" 0201L 1211.37,1072 r90 top value=0.1uF
C4 "GRM033R71E101KA01D" 0201 1152,1105 r180 top value=100pF
C5 "GRM033Z71C104KE14D" 0201L 1152,1058 r90 bottom value=0.1uF
C6 "GRM033Z71C104KE14D" 0201L 1090.37,1072 r90 top value=0.1uF
C7 "GRM033Z71C104KE14D" 0201L 1155,869.5 r270 bottom value=0.1uF
C8 "GRM033Z71C104KE14D" 0201L 1079.06,1082.98 r0 top value=0.1uF
C9 "GRM033Z71C104KE14D" 0201L 1079.06,1642.95 r0 top value=0.1uF
C10 "GRM033Z71C104KE14D" 0201L 1142,2430.08 r270 bottom value=0.1uF
C11 "GRM033Z71C104KE14D" 0201L 1090.09,1653.98 r270 top value=0.1uF
C12 "GRM033R71E101KA01D" 0201 1151,1620 r0 top value=100pF
C13 "GRM033Z71C104KE14D" 0201L 1151,1630 r270 bottom value=0.1uF
C14 "GRM033Z71C104KE14D" 0201L 1213,1652 r270 top value=0.1uF
C15 "GRM033Z71C104KE14D" 0201L 1153,1830.75 r90 bottom value=0.1uF
C16 "GRM033Z71C104KE14D" 0201L 1222.39,1642.95 r180 top value=0.1uF
C17 "GRM155R61E104KA87D" 0402 2979,502 r270 bottom value=0.1uF
C18 "GRM155R61E104KA87D" 0402 1563,1396 r0 bottom value=0.1uF
C19 "GRM155R61E104KA87D" 0402 2759,450 r0 bottom value=0.1uF
C20 "GRM155R61E104KA87D" 0402 2895,481 r180 bottom value=0.1uF
C21 "GRM033Z71C104KE14D" 0201L 967.44,1389.67 r0 top value=0.1uF
C22 "GRM155R61E104KA87D" 0402 3017,627.15 r270 bottom value=0.1uF
C23 "GRM033Z71C104KE14D" 0201L 347.64,1359.3 r0 bottom value=0.1uF
C24 "GRM033Z71C104KE14D" 0201L 963.44,1359.65 r180 top value=0.1uF
C25 "GRM1555C1E390JA01D" 0402 899,1358 r270 top value=39pF
C26 "GRM033Z71C104KE14D" 0201L 967.44,1329.63 r0 top value=0.1uF
C27 "GRM152R60J105ME15D" 0402 2201.5,499 r180 top value=1uF
C28 "GRM188R61E475KE11D" 0603 2346.26,538 r270 top value=4.7uF
C29 "GRM033R61E104KE14J" 0201_033 2414.16,557 r270 top value=0.1uF
C30 "GRM033R61E104KE14J" 0201_033 2562,203 r0 bottom value=0.1uF
C31 "GRM152R60J105ME15D" 0402 2162,689 r180 bottom value=1uF
C32 "GRM188R61E475KE11D" 0603 2265.94,628 r180 bottom value=4.7uF
C33 "GRM033R61E104KE14J" 0201_033 2366.5,650.15 r0 bottom value=0.1uF
C34 "GRM152R60J105ME15D" 0402 2405,966 r180 bottom value=1uF
C35 "GRM188R61E475KE11D" 0603 2484.32,890 r90 bottom value=4.7uF
C36 "GRM033R61E104KE14J" 0201_033 2447,811.75 r0 bottom value=0.1uF
C37 "GRM033Z71C104KE14D" 0201L 1319,1471 r0 top value=0.1uF
C38 "GRM033Z71C104KE14D" 0201L 1331,1281 r0 bottom value=0.1uF
C39 "GRM188Z71A106MA73D" 0603L 1327.87,1448.56 r0 bottom value=10uF
C40 "GRM033Z71C104KE14D" 0201L 1111,1383 r0 bottom value=0.1uF
C41 "GRM033Z71C104KE14D" 0201L 1195,1282 r90 bottom value=0.1uF
C42 "GRM033Z71C104KE14D" 0201L 1191,1463 r270 bottom value=0.1uF
C43 "GRM188Z71A106MA73D" 0603L 1163,1262 r90 bottom value=10uF
C44 "GRM188Z71A106MA73D" 0603L 1023.33,1479 r90 top value=10uF
C45 "GRM033Z71C104KE14D" 0201L 1057,1410 r90 top value=0.1uF
C46 "GRM155R70J105MA12D" 0402L 975,1151 r180 bottom value=1uF
C47 "GRM188Z71A106MA73D" 0603L 845.62,1055 r180 bottom value=10uF
C48 "GRM033Z71C104KE14D" 0201L 1023.33,1213.57 r270 bottom value=0.1uF
C49 "GRM155R61E104KA87D" 0402 1482.25,435.62 r180 bottom value=0.1uF
C50 "GRM155R61E104KA87D" 0402 1059,686 r0 bottom value=0.1uF
C51 "GRM1555C1E330JA01D" 0402 1153.37,793 r180 bottom value=33pF
C52 "GRM1555C1H181JA01D" 0402 1154,926.1 r180 bottom value=180pF
C53 "GRM155R61E104KA87D" 0402 822,431.62 r180 bottom value=0.1uF
C54 "GRM155R61E104KA87D" 0402 932,2388 r180 bottom value=0.1uF
C55 "GRM155R61E104KA87D" 0402 1219,2051 r90 bottom value=0.1uF
C56 "GRM1555C1E330JA01D" 0402 1149.37,1960 r0 bottom value=33pF
C57 "GRM1555C1H181JA01D" 0402 1151.07,1779 r0 bottom value=180pF
C58 "GRM155R61E104KA87D" 0402 1366.5,2384.38 r180 bottom value=0.1uF
C59 "GRM155R61E104KA87D" 0402 1303,527 r270 bottom value=0.1uF
C60 "GRM155R61E104KA87D" 0402 1302,658 r90 bottom value=0.1uF
C61 "GRM155R61E104KA87D" 0402 941,2109.58 r270 bottom value=0.1uF
C62 "GRM155R61E104KA87D" 0402 1026.09,2109.58 r270 bottom value=0.1uF
C63 "GRM155R61E104KA87D" 0402 1313,2230.5 r0 bottom value=0.1uF
C64 "GRM155R61E104KA87D" 0402 1315,2137 r0 bottom value=0.1uF
C65 "GRM155R61E104KA87D" 0402 973,565 r180 bottom value=0.1uF
C66 "GRM155R61E104KA87D" 0402 974,612 r180 bottom value=0.1uF
C67 "GRM32ER61A476KE20L" 1210_270 2594,2441 r0 bottom value=47uF
C68 "JMK212BJ226MG-T" 0805_HV 2576,2553 r0 bottom value=22uF
C69 "GRM188R61A106ME69D" 0603 2420.29,2466 r0 bottom value=10uF
C70 "GRM152R60J105ME15D" 0402 2104,2551 r90 bottom value=1uF
C71 "C1005X5R1A475K050BC" 0402L 525.23,2177.39 r180 bottom value="4.7 µF"
C72 "C1005X5R1A475K050BC" 0402L 1614.36,2111.41 r180 bottom value="4.7 µF"
C73 "C1005X6S1A105K050BC" 0402L 511.06,2422.62 r180 bottom value="1 µF"
C74 "GRM033R61E104KE14J" 0201_033 682.35,2115.51 r270 bottom value=0.1uF
C75 "GRM152R60J105ME15D" 0402 845,1978 r270 bottom value=1uF
C76 "GRM033R61E104KE14J" 0201_033 887,1988 r270 bottom value=0.1uF
C77 "C1005X6S1A105K050BC" 0402L 1600.19,2356.65 r180 bottom value="1 µF"
C78 "GRM033R61E104KE14J" 0201_033 1680.51,2073 r180 bottom value=0.1uF
C79 "GRM152R60J105ME15D" 0402 1816,2261 r0 bottom value=1uF
C80 "GRM033R61E104KE14J" 0201_033 1905.33,2270.01 r0 bottom value=0.1uF
C81 "GRM188R60J475KE19D" 0603 2026.78,444 r90 bottom value=4.7uF
C82 "GRM188R60J475KE19D" 0603 612,2290 r0 bottom value=4.7uF
C83 "885012206052" 0603 2281,2361 r0 bottom value=1uF
C84 "885012206052" 0603 2167,2291 r90 bottom value=1uF
C85 "885012207026" 0805_HV 1945,2073 r0 bottom value=10uF
C86 "GRM033Z71C104KE14D" 0201L 2272.09,2066 r270 bottom value=0.1uF
C87 "JMK212BJ226MG-T" 0805_HV 1947,616 r0 bottom value=22uF
C88 "885012207026" 0805_HV 1644,411 r270 bottom value=10uF
C89 "JMK212BJ226MG-T" 0805_HV 730,2313 r90 bottom value=22uF
C90 "885012207026" 0805_HV 874,2102 r270 top value=10uF
C91 "GRM188R60J475KE19D" 0603 1901,520 r180 top value=4.7uF
C92 "GRM188R60J475KE19D" 0603 660.31,2200 r270 bottom value=4.7uF
C93 "885012207026" 0805_HV 1910,233 r0 bottom value=10uF
C94 "885012207026" 0805_HV 1768.78,355 r180 bottom value=10uF
C95 "885012207026" 0805_HV 392.5,2110.01 r270 top value=10uF
C96 "885012207026" 0805_HV 481.5,2110.01 r270 top value=10uF
C97 "GRM033Z71C104KE14D" 0201L 709.78,1567 r90 bottom value=0.1uF
C98 "GRM033R71E101JA01D" 0201_033L 956.5,1536 r0 top value=100pF
C99 "GRM188Z71A106MA73D" 0603L 756.78,1583 r90 bottom value=10uF
C100 "GRM033Z71C104KE14D" 0201L 2073,898 r90 bottom value=0.1uF
C101 "GRM188Z71A106MA73D" 0603L 806,1639 r90 bottom value=10uF
C102 "GRM155R61E104KA87D" 0402 895,1753 r270 bottom value=0.1uF
C103 "GRM155R61E104KA87D" 0402 1953,2083.5 r270 top value=0.1uF
C104 "C3216X5R0J107M160AB" 1206_190 2582,2339 r0 top value=100uF
C105 "GRM033Z71C104KE14D" 0201L 2612,2317 r270 bottom value=0.1uF
C106 "GRM033Z71C104KE14D" 0201L 2710,1907.59 r90 bottom value=0.1uF
C107 "GRM033Z71C104KE14D" 0201L 2403,2131 r0 bottom value=0.1uF
C108 "C1608X5R1E335K080AC" 0603 2447,2357 r90 bottom value=3.3uF
C109 "GRM033Z71C104KE14D" 0201L 2802,2230 r180 bottom value=0.1uF
C110 "GRM033Z71C104KE14D" 0201L 2403,2032 r0 bottom value=0.1uF
C111 "GRM188Z71C475KE21D" 0603 2897,2055 r270 bottom value=4.7uF
C112 "GRM033Z71C104KE14D" 0201L 2798,2081 r90 bottom value=0.1uF
C113 "GRM188Z71C475KE21D" 0603 2865,2263 r90 bottom value=4.7uF
C114 "GRM033Z71C104KE14D" 0201L 2915,2242 r270 bottom value=0.1uF
C115 "GRM033Z71C104KE14D" 0201L 1893,1865 r0 top value=0.1uF
C116 "GRM033Z71C104KE14D" 0201L 1796.24,1912 r90 top value=0.1uF
C117 "CC0201JRNPO8BN101" 0201L 2820,2040.38 r270 bottom value=100pF
C118 "C1005C0G1H180J050BA" 0402L 2758,2283 r90 top value=18pF
C119 "C1005C0G1H180J050BA" 0402L 2986,2130 r90 top value=18pF
C120 "GRM033Z71C104KE14D" 0201L 2403,2153.12 r0 bottom value=0.1uF
C121 "GRM033Z71C104KE14D" 0201L 2308.59,1845 r270 top value=0.1uF
C122 "GRM033Z71C104KE14D" 0201L 2532,1785 r90 bottom value=0.1uF
C123 "GRM033Z71C104KE14D" 0201L 2226,2071 r270 bottom value=0.1uF
C124 "GRM033Z71C104KE14D" 0201L 2480,1720 r0 bottom value=0.1uF
C125 "0402ZC103JAT2A" 0402L 460.07,2442.31 r270 bottom value="10000 pF"
C126 "0402ZC103JAT2A" 0402L 1549.2,2376.33 r270 bottom value="10000 pF"
D1 "LTST-C150KGKT" LTST-C150_1206_Green 2247,1030 r0 top value=Green
D2 "LTST-C150KGKT" LTST-C150_1206_Green 2418,2502 r180 top value=Green
FB1 "NFM31PC276B0J3L" Murata_NFM31P 2189,2449 r180 bottom value="27 uF"
FB2 "NFM31PC276B0J3L" Murata_NFM31P 764,2060.89 r270 bottom value="27 uF"
FB3 "NFM31PC276B0J3L" Murata_NFM31P 1704,2188.21 r90 bottom value="27 uF"
FID1 "Fiducial" Fiducial10-20#1 3885,115 r0 top
FID2 "Fiducial" Fiducial10-20#1 147,464 r0 top
FID3 "Fiducial" Fiducial10-20#2 3278,2563 r0 top
H1 "NY PMS 440 0025 PH" "NY PMS 440 0025 PH" 175,2575 r0 top
H2 "NY PMS 440 0025 PH" "NY PMS 440 0025 PH" 175,175 r0 top
H3 "1902E" Keystone_1902E 200,2550 r180 bottom locked
H4 "1902E" Keystone_1902E 200,200 r180 bottom locked
J1 "142-0701-801" Johnson_142-0701-801#1 1528.13,110 r180 top
J2 "901-144-8RFX" AMPHENOL_901-144-8RFX 1153.37,203 r90 top
J3 "142-0701-801" Johnson_142-0701-801#1 778.13,110 r180 top
J4 "142-0701-801" Johnson_142-0701-801#1 757,2640 r0 top
J5 "901-144-8RFX" AMPHENOL_901-144-8RFX 1142,2547 r0 top
J6 "142-0701-801" Johnson_142-0701-801#1 1528,2640 r0 top
J7 "901-144-8RFX" AMPHENOL_901-144-8RFX 3164,349 r0 top
J8 "142-0701-801" Johnson_142-0701-801#2 110,1734.25 r90 top
J9 "901-144-8RFX" AMPHENOL_901-144-8RFX 200,1359.65 r90 top
J10 "142-0701-801" Johnson_142-0701-801#1 110,984.25 r90 top
J11 "901-144-8RFX" AMPHENOL_901-144-8RFX 2760,877 r0 top
J12 "901-144-8RFX" AMPHENOL_901-144-8RFX 3091,877 r0 top
J13 "87224-3" TE_87224-3 654,936 r270 top
J14 "87224-3" TE_87224-3 162,2084 r0 top
J15 "ASP-134488-01" Samtec_ASP-134488-01 3652,1375 r180 bottom
J16 "87224-3" TE_87224-3 2510,2659 r0 top
J17 "1734035-2" CONN_USB-Mini-B-1734035-2 2996,2537 r180 top
L1 "LQG15HSR18J02D" IND_LQG15H 1237,1187 r90 top value=180nH
L2 "LQG15HSR18J02D" IND_LQG15H 1152,1139 r0 top value=180nH
L3 "LQG15HSR18J02D" IND_LQG15H 1063.79,1187 r90 top value=180nH
L4 "LQG15HSR18J02D" IND_LQG15H 1071.55,1571 r270 top value=180nH
L5 "LQG15HSR18J02D" IND_LQG15H 1151.37,1581.05 r180 top value=180nH
L6 "LQG15HSR18J02D" IND_LQG15H 1233.42,1571 r270 top value=180nH
L7 "LQG15WZ43NG02D" LQG15WZ_02 858,1358 r90 top value=43nH
L8 "BLM18KG121TH1D" 0603 2283.89,538 r90 top value="120 ohm"
L9 "BLM18KG121TH1D" 0603 2265.94,688 r0 bottom value="120 ohm"
L10 "BLM18KG121TH1D" 0603 2431.2,890 r270 bottom value="120 ohm"
L11 "LQG15HSR22J02D" IND_LQG15H 1188.56,866 r90 bottom value=220nH
L12 "LQG15HSR22J02D" IND_LQG15H 1121.51,867 r90 bottom value=220nH
L13 "LQG15HSR22J02D" IND_LQG15H 1105.47,1850 r270 bottom value=220nH
L14 "LQG15HSR22J02D" IND_LQG15H 1199.04,1850 r270 bottom value=220nH
L15 "74279271" 0402 2420,2528 r180 bottom value="120 ohm"
L18 "74279271" 0402 2166,2156 r270 bottom value="120 ohm"
L19 "74279271" 0402 2984,2086 r180 bottom value="120 ohm"
L20 "74279271" 0402 2877,2169.5 r180 bottom value="120 ohm"
LBL1 "THT-14-423-10" Label_650x200 2724,1357.38 r0 top
Logo1 "Texas Instruments" TI_Stacked_Overlay_Small 3048.84,1599.84 r0 top
Logo2 "CE Mark" CE_Mark_5mm 2681,1297 r180 bottom
Logo3 "FCC disclaimer" FCC_disclaimer 3315,2511 r180 bottom
Logo4 "WEEE logo" WEEE_Minimum 3060,1347 r180 bottom
R1 "CRCW02010000Z0ED" 0201L 1221.74,1106 r180 top value=0
R2 "CRCW02010000Z0ED" 0201L 1477.72,290 r0 bottom value=0
R3 "CRCW02010000Z0ED" 0201L 1187,1094 r90 top value=0
R4 "RC0201FR-7D33RL" 0201 1200,1154 r90 top value=33.0
R5 "RC0201FR-7D10RL" 0201 1163.85,1226 r90 top value=10.0
R6 "CRCW02010000Z0ED" 0201L 1199,1210 r180 top value=0
R7 "RC0201FR-0725R5L" 0201L 1175.69,1096 r0 bottom value=25.5
R8 "RC0201FR-0725R5L" 0201L 1128,1096 r0 bottom value=25.5
R9 "CRCW02010000Z0ED" 0201L 1101,1210 r0 top value=0
R10 "CRCW02010000Z0ED" 0201L 1116.13,1094 r90 top value=0
R11 "RC0201FR-7D33RL" 0201 1100.69,1154 r90 top value=33.0
R12 "RC0201FR-7D10RL" 0201 1142,1226 r90 top value=10.0
R13 "CRCW02010000Z0ED" 0201L 827,291 r180 bottom value=0
R14 "CRCW02010000Z0ED" 0201L 1079.57,1106 r0 top value=0
R15 "CRCW02010000Z0ED" 0201L 1085,1619 r0 top value=0
R16 "CRCW02010000Z0ED" 0201L 867.5,2325.5 r90 bottom value=0
R17 "CRCW02010000Z0ED" 0201L 1116.13,1631 r270 top value=0
R18 "RC0201FR-7D33RL" 0201 1103,1575 r270 top value=33.0
R19 "RC0201FR-7D10RL" 0201 1141,1520 r270 top value=10.0
R20 "CRCW02010000Z0ED" 0201L 1108,1534 r0 top value=0
R21 "RC0201FR-0725R5L" 0201L 1128.3,1590 r180 bottom value=25.5
R22 "RC0201FR-0725R5L" 0201L 1174.05,1590 r180 bottom value=25.5
R23 "CRCW02010000Z0ED" 0201L 1197,1534 r180 top value=0
R24 "CRCW02010000Z0ED" 0201L 1187,1631 r270 top value=0
R25 "RC0201FR-7D33RL" 0201 1203,1575 r270 top value=33.0
R26 "RC0201FR-7D10RL" 0201 1163,1520 r270 top value=10.0
R27 "CRCW02010000Z0ED" 0201L 1436.5,2318.5 r90 bottom value=0
R28 "CRCW02010000Z0ED" 0201L 1224,1619 r180 top value=0
R29 "RC0201FR-7D49R9L" 0201L 849.15,1428 r270 bottom value=49.9
R30 "RC0201FR-7D49R9L" 0201L 967,1420 r0 top value=49.9
R31 "CRCW02010000Z0ED" 0201L 513.05,2094.07 r0 bottom value=0
R32 "CRCW02010000Z0ED" 0201L 2672,666 r180 top value=0
R33 "CRCW02010000Z0ED" 0201L 502,2026 r90 bottom value=0
R34 "CRCW040256K2FKED" 0402 2894.38,526 r180 bottom value=56.2k
R35 "CRCW02010000Z0ED" 0201L 2672,666 r180 bottom value=0
R36 "CRCW02010000Z0ED" 0201L 2672,642 r180 bottom value=0
R37 "CRCW040224K9FKED" 0402 3061.38,525.62 r180 bottom value=24.9k
R38 "RC0201FR-071KL" 0201L 249,1653.98 r270 bottom value=1.00k
R39 "RC0201FR-071KL" 0201L 250,1786 r270 bottom value=1.00k
R40 "CRCW02010000Z0ED" 0201L 2672,642 r180 top value=0
R41 "CRCW02010000Z0ED" 0201L 917,1459 r0 bottom value=0
R42 "CRCW040256K2FKED" 0402 2794,524 r270 bottom value=56.2k
R43 "CRCW02010000Z0ED" 0201L 817,1386.6 r270 top value=0
R44 "CRCW040224K9FKED" 0402 2738,524 r90 bottom value=24.9k
R45 "CRCW02010000Z0ED" 0201L 747,1385 r270 top value=0
R46 "RC0201FR-7D49R9L" 0201L 998.44,1378.65 r90 top value=49.9
R47 "RC0201FR-7D49R9L" 0201L 938.44,1378.65 r270 top value=49.9
R48 "RC0201FR-7D10RL" 0201L 736,1373 r0 top value=10.0
R49 "RC0201FR-7D10RL" 0201L 735,1341.27 r0 top value=10.0
R50 "RC0201FR-7D49R9L" 0201L 938.44,1340.65 r270 top value=49.9
R51 "CRCW02010000Z0ED" 0201L 747,1329 r90 top value=0
R52 "CRCW02010000Z0ED" 0201L 1657,1488 r180 bottom value=0
R53 "CRCW02010000Z0ED" 0201L 817,1330.22 r90 top value=0
R54 "CRCW02010000Z0ED" 0201L 999,1319.2 r90 top value=0
R55 "CRCW02010000Z0ED" 0201L 1714,1488.19 r180 bottom value=0
R56 "RC0201FR-7D4K7L" 0201 2283,790 r90 bottom value=4.70k
R57 "RMCF0603ZT0R00" 0603 2106,852.62 r0 bottom value=0
R58 "RC0201FR-7D4K7L" 0201 2270,745 r0 bottom value=4.70k
R59 "RC0402FR-071KL" 0402 2317,831.38 r270 bottom value=1.00k
R60 "CRCW02010000Z0ED" 0201L 2374,448 r270 top value=0
R61 "CRCW02010000Z0ED" 0201L 2554.35,1033.02 r0 top value=0
R62 "RC0201FR-7D4K7L" 0201 2452,658 r270 bottom value=4.70k
R63 "CRCW02010000Z0ED" 0201L 2394.47,448 r270 top value=0
R64 "CRCW02010000Z0ED" 0201L 2554.35,1013.02 r0 top value=0
R65 "RC0201FR-7D49R9L" 0201L 2520.87,417 r90 bottom value=49.9
R66 "RC0201FR-071KL" 0201L 2049,229 r90 bottom value=1.00k
R67 "RC0201FR-7D49R9L" 0201L 2532.5,458 r180 bottom value=49.9
R68 "CRCW02010000Z0ED" 0201L 2050,304 r180 bottom value=0
R69 "RC0201FR-071KL" 0201L 2049,173 r90 bottom value=1.00k
R70 "CRCW02010000Z0ED" 0201L 2405,486 r0 top value=0
R71 "RC0201FR-7D4K7L" 0201 2491,668.47 r0 bottom value=4.70k
R72 "RC0201FR-7D4K7L" 0201 2549,726 r0 bottom value=4.70k
R73 "RC0201FR-7D4K7L" 0201 2290,668 r0 top value=4.70k
R74 "RC0201FR-7D4K7L" 0201 2483,724 r0 bottom value=4.70k
R75 "CRCW02010000Z0ED" 0201L 1063.87,1333.62 r0 top value=0
R76 "CRCW02010000Z0ED" 0201L 1064,1243 r0 bottom value=0
R77 "CRCW02010000Z0ED" 0201L 1075,1494 r0 bottom value=0
R78 "ERJ-1GN0R00C" 0201L 1023.33,1543 r270 top value=0
R79 "ERJ-1GN0R00C" 0201 985.71,1494 r270 bottom value=0
R80 "CRCW0402499RFKED" 0402 1208.45,457 r90 bottom value=499
R81 "CRCW04020000Z0ED" 0402 1482.38,387.5 r0 bottom value=0
R82 "CRCW040259R0FKED" 0402 1403.38,415 r90 bottom value=59.0
R83 "CRCW040249R9FKED" 0402 1349.38,414.87 r90 bottom value=49.9
R84 "CRCW040237R4FKED" 0402 1175,718 r90 bottom value=37.4
R85 "CRCW04020000Z0ED" 0402 1389.45,726 r270 bottom value=0
R86 "CRCW0402200RFKED" 0402 1297.49,415 r90 bottom value=200
R87 "CRCW0402442RFKED" 0402 1154,977.1 r0 bottom value=442
R88 "CRCW0402200RFKED" 0402 1006.38,410 r90 bottom value=200
R89 "ERJ-2RKF4701X" 0402 1389.45,826 r270 bottom value=4.70k
R90 "CRCW040237R4FKED" 0402 1129,718 r90 bottom value=37.4
R91 "CRCW040259R0FKED" 0402 899,409 r270 bottom value=59.0
R92 "CRCW040249R9FKED" 0402 955.5,409 r270 bottom value=49.9
R93 "CRCW02010000Z0ED" 0201L 969,645 r180 bottom value=0
R94 "CRCW04020000Z0ED" 0402 822.5,383 r180 bottom value=0
R95 "CRCW02010000Z0ED" 0201L 1426,518 r90 bottom value=0
R96 "CRCW0402499RFKED" 0402 1096.8,458 r90 bottom value=499
R97 "CRCW0402499RFKED" 0402 1093.32,2313 r270 bottom value=499
R98 "CRCW04020000Z0ED" 0402 932,2437 r0 bottom value=0
R99 "CRCW040259R0FKED" 0402 907.7,2316 r90 bottom value=59.0
R100 "CRCW040249R9FKED" 0402 958,2316 r90 bottom value=49.9
R101 "CRCW040237R4FKED" 0402 1124.45,2050 r270 bottom value=37.4
R102 "CRCW04020000Z0ED" 0402 1045.9,1988 r180 bottom value=0
R103 "CRCW0402200RFKED" 0402 1004,2315.38 r90 bottom value=200
R104 "CRCW0402442RFKED" 0402 1152,1726 r180 bottom value=442
R105 "CRCW0402200RFKED" 0402 1291,2313 r90 bottom value=200
R106 "ERJ-2RKF4701X" 0402 1046.9,2039 r0 bottom value=4.70k
R107 "CRCW040237R4FKED" 0402 1174.9,2050 r270 bottom value=37.4
R108 "CRCW02010000Z0ED" 0201L 1291.38,2090 r270 bottom value=0
R109 "CRCW040259R0FKED" 0402 1341,2314 r270 bottom value=59.0
R110 "CRCW040249R9FKED" 0402 1392,2314 r270 bottom value=49.9
R111 "CRCW04020000Z0ED" 0402 1366.5,2432.5 r180 bottom value=0
R112 "CRCW02010000Z0ED" 0201L 897,2119 r90 bottom value=0
R113 "CRCW0402499RFKED" 0402 1204,2312 r270 bottom value=499
R114 "RC0402FR-071KL" 0402 2271,2544 r90 bottom value=1.00k
R115 "Resistor" 0402 577.38,2128.5 r0 bottom value=0
R116 "ERJ-2RKF1002X" 0402L 404.8,2422.62 r180 bottom value="10 kΩ"
R117 "Resistor" 0402 1594.68,2047.79 r270 bottom value=0
R118 "ERJ-2RKF1002X" 0402L 1493.93,2356.65 r180 bottom value="10 kΩ"
R119 "ERJ-2RKF1272X" 0402L 485.86,2212.39 r0 bottom value="12.7 kΩ"
R120 "ERJ-2RKF1272X" 0402L 1574.99,2146.41 r0 bottom value="12.7 kΩ"
R121 "ERJ-2RKF1002X" 0402L 424.48,2442.31 r270 bottom value="10 kΩ"
R122 "ERJ-2RKF1002X" 0402L 1513.61,2376.33 r270 bottom value="10 kΩ"
R123 "RK73Z1ETTP" 0402 1750,614.98 r180 bottom value=0
R124 "RK73Z1ETTP" 0402 785,2239 r0 top value=0
R125 "RK73Z1ETTP" 0402 1808.78,257 r90 bottom value=0
R126 "RK73Z1ETTP" 0402 439.5,2213.01 r0 top value=0
R127 "RC0201FR-071KL" 0201L 1005.4,1583.02 r90 top value=1.00k
R128 "RC0201FR-07499RL" 0201L 956.5,1514.95 r180 top value=499
R129 "RC0201JR-072RL" 0201L 913.5,1525.98 r270 top value=2.0
R130 "CRCW02010000Z0ED" 0201L 926.5,1487.98 r0 top value=0
R131 "RC0201FR-079K76L" 0201L 841,1556.02 r0 top value=9.76k
R132 "RC0201FR-0714K3L" 0201L 842,1531 r0 top value=14.3k
R133 "ERJ-L03KF50MV" 0603 776,1890.08 r90 bottom value=0.05
R134 "ERJ-L03KF50MV" 0603 1793,2161.06 r90 bottom value=0.05
R135 "CRCW02010000Z0ED" 0201L 1909,1733 r180 top value=0
R136 "CRCW02010000Z0ED" 0201L 1909,1771 r180 top value=0
R137 "CRCW02010000Z0ED" 0201L 2494,1837 r180 top value=0
R138 "CRCW02010000Z0ED" 0201L 2494,1882 r180 top value=0
R139 "CRCW02010000Z0ED" 0201L 1909,1810 r180 top value=0
R140 "RC0201FR-7D49R9L" 0201L 2814,1948 r270 bottom value=49.9
R141 "CRCW02010000Z0ED" 0201L 1909,1752 r180 top value=0
R142 "CRCW02010000Z0ED" 0201L 1909,1790 r180 top value=0
R143 "CRCW02010000Z0ED" 0201L 2494,1860 r180 top value=0
R144 "CRCW02010000Z0ED" 0201L 2494,1902 r180 top value=0
R145 "CRCW02010000Z0ED" 0201L 2561.99,1921.57 r180 bottom value=0
R146 "CRCW02010000Z0ED" 0201L 1909,1830 r180 top value=0
R147 "RK73H1ETTP10R0F" 0402 3038,2251 r270 top value=10.0
R148 "CRCW02010000Z0ED" 0201L 2424,1883 r180 bottom value=0
R149 "RC0201FS-7D10KL" 0201L 1835,1911 r0 top value=10.0k
R150 "RK73H1ETTP10R0F" 0402 2986,2250 r270 top value=10.0
R151 "CRCW02010000Z0ED" 0201L 2422,1947 r180 bottom value=0
R152 "CRCW02010000Z0ED" 0201L 1893,1911 r180 top value=0
R153 "CRCW02010000Z0ED" 0201L 1893,1888 r180 top value=0
R154 "RC0201FR-7D12KL" 0201L 2947,2180 r270 bottom value=12.0k
R155 "RC0201FS-7D1KL" 0201L 2851,2041 r90 bottom value=1.00k
R156 "CRCW04022K00JNED" 0402 2094,1777 r270 bottom value=2.0k
R157 "CRCW04022K00JNED" 0402 2146,1983 r270 bottom value=2.0k
R158 "CRCW02010000Z0ED" 0201L 2671.29,1896 r270 bottom value=0
R159 "CRCW02010000Z0ED" 0201L 2635,1895 r270 bottom value=0
R160 "RC0201FR-7D10KL" 0201L 2417,2386 r90 top value=10.0k
R161 "RC0201FR-7D10KL" 0201L 2387,2385.02 r90 top value=10.0k
R162 "RC0201FR-7D10KL" 0201L 2324,2379 r90 top value=10.0k
R163 "CRCW02010000Z0ED" 0201L 2598,1896 r270 bottom value=0
R164 "RC0201FR-7D2K2L" 0201L 2362,2385 r270 top value=2.20k
R165 "RC0201FR-7D10KL" 0201L 2588,1660 r90 bottom value=10.0k
R166 "RC0201FR-7D10KL" 0201L 2526,1660 r90 bottom value=10.0k
R167 "CRCW02010000Z0ED" 0201L 2618,1660 r90 bottom value=0
R168 "CRCW02010000Z0ED" 0201L 2754,1606 r180 bottom value=0
R169 "CRCW02010000Z0ED" 0201L 2526,1716.12 r90 bottom value=0
R170 "CRCW02010000Z0ED" 0201L 2480,1770.61 r180 bottom value=0
R171 "RC0603JR-070RL" 0603L 694.76,411.6 r0 top value=0
R172 "RC0603JR-070RL" 0603L 694.76,486.4 r0 top value=0
R173 "RC0402JR-070RL" 0402L 2428.97,1677.34 r0 bottom value=0
R174 "RC0402JR-070RL" 0402L 2449.02,1657.31 r90 bottom value=0
R175 "ERJ-2RKF1002X" 0402L 446.49,2177.39 r0 bottom value="10 kΩ"
R176 "ERJ-2RKF1002X" 0402L 1535.62,2111.41 r0 bottom value="10 kΩ"
S1 "EVQ-5PN04K" SW_EVQ5PN04K 379,552 r270 top
T1 "ADT4-1WT+" MNC_CD542 1153.37,570 r90 top
T2 "ADT4-1WT+" MNC_CD542 1153.37,892 r270 top
T3 "ADT4-1WT+" MNC_CD542 1151,2191 r270 top
T4 "ADT4-1WT+" MNC_CD542 1151,1827.76 r90 top
T5 "ADT1-6T+" FP-ADT1-6T+_SMD6-MFG 531,1361 r270 top
TP1 "5011" Keystone5011 2217,855 r0 top
TP2 "5013" Keystone5013 873,974.8 r90 top
TP3 "5011" Keystone5011 147,623 r90 top
TP4 "5011" Keystone5011 1875,2645.5 r90 top
TP5 "5011" Keystone5011 1554,802 r90 top
TP6 "5010" Keystone5010 649,671 r90 top
TP7 "5010" Keystone5010 1652,1718 r90 top
TP8 "5010" Keystone5010 790,1768 r90 top
TP9 "5010" Keystone5010 875,766 r0 top
TP10 "5010" Keystone5010 1554,629 r0 top
TP11 "5010" Keystone5010 1439,2005 r0 top
TP12 "5010" Keystone5010 117,2250 r0 top
TP13 "5010" Keystone5010 2208,2655 r0 top
U1 "SN65LVDS100DGKR" DGK0008A_L 2818,653.15 r180 bottom
U2 "HD3SS3411IRWAT" RWA0014A 1696.48,1390.04 r0 bottom
U3 "CDCE6214WRGERQ1" RGE0024P 2424,697 r90 top
U4 "ADC3683IRSBT" RSB0040B 1200.12,1374.54 r0 top
U5 "TPS3125J18DBV" DBV0005A_L 567,449 r180 top
U6 "THS4541IRGTR" RGT0016A_NV 1151.92,586.12 r90 bottom
U7 "THS4541IRGTR" RGT0016A_NV 1149.84,2184 r270 bottom
U8 "TPS7A8001ADRBR" DRB0008A 472.87,2317.5 r90 bottom
U9 "TPS7A8001ADRBR" DRB0008A 1562,2251.53 r90 bottom
U10 "LM7705MM/NOPB" DGK0008A_N 1918.78,443 r90 bottom
U11 "LM7705MM/NOPB" DGK0008A_N 610.5,2251.5 r0 top
U12 "TLV70233DBVR" DBV0005A_N 2287,2203 r270 bottom
U13 "OPA837IDBVR" DBV0006A_N 895,1627 r0 top
U14 "REF3318AIDCKR" DCK0003A_N 758,1621 r90 top
U15 "INA226AIDGSR" DGS0010A_L 934,1865.08 r180 bottom
U16 "INA226AIDGSR" DGS0010A_L 1976,2186.5 r180 bottom
U17 "FT4232H-56Q-TRAY" VQFN-56 2602.02,2121 r180 bottom
U18 "LSF0204RUTR" RUT0012A 1824,1833.29 r0 top
U19 "SN74LVC1G125DCKT" DCK0005A_N 2399,1882 r180 top
U20 "SN74LVC1G125DCKT" DCK0005A_N 2625.11,1743.62 r180 bottom
U21 "93LC46B-I/ST" TSSOP-8 2374,2179 r270 top
U22 "SN74LVC1G125DCKT" DCK0005A_N 2809,1745 r0 bottom
U23 "SN74LVC1G125DCKT" DCK0005A_N 2376,1745.02 r0 bottom
Y1 "KC3225A19.2000C3GE00" Kyocera_KC3225A 620,2002 r270 bottom
Y2 "ABLNO-V-125.000MHZ-T2" Abracon_ABLNO 500,1793 r0 bottom
Y3 "ECS-100-12-33-AGN-TR" FP-ECS-100-12-33-AGN-TR_XTAL_SMD_3MM2_2MM5-MFG 2308,342 r270 top
Y4 "CVHD-957-10.000" FP-CVHD-957-10.000_SMT_XTAL_14MM2_9MM14-MFG 2301,303 r90 bottom
Y5 "ABM3-12.000MHZ-D2Y-T" XTAL_ABM3 2861,2192 r270 top
ZZ1 "This Assembly Note is for PCB labels only" AssemblyNoteLabel 57.28,5608 r0 top
ZZ2 "These assemblies are ESD sensitive, ESD precautions shall be observed." AssemblyNote 57.28,5508 r0 top
ZZ3 "These assemblies must be clean and free from flux and all contaminants. Use of no clean flux is not acceptable." AssemblyNote 56,5390 r0 top

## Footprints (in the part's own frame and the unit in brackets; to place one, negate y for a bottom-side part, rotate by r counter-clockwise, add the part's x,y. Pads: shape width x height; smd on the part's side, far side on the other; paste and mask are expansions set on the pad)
0201 [mm] "Data from Kemet datasheet CC101_COM dated 7/28/11"
  rect 0.46x0.42 smd mask+0.048: 1(-0.33,0) 2(0.33,0)
  body extent -0.31,-0.16 0.31,0.16, height 0.26
0201_033 [mm] "SMD, 2-Leads, Height 0.33mm"
  rect 0.46x0.42 smd mask+0.048: 1(-0.33,0) 2(0.33,0)
  body extent -0.31,-0.16 0.31,0.16, height 0.33
0201_033L [mm] "0201"
  rect 0.36x0.32 smd mask+0.048: 1(-0.28,0) 2(0.28,0)
  body extent -0.31,-0.16 0.31,0.16, height 0.33
0201L [mm] "Data from Kemet datasheet CC101_COM dated 7/28/11"
  rect 0.36x0.32 smd mask+0.048: 1(-0.28,0) 2(0.28,0)
  body extent -0.31,-0.16 0.31,0.16, height 0.26
0402 [mm] "0402 from SM-752 data"
  rect 0.8x0.6 smd: 1(-0.6,0) 2(0.6,0)
  silkscreen extent -1.22,-0.52 1.22,0.52, body extent -0.55,-0.3 0.55,0.3, height 0.6
0402L [mm] "0402 from SM-752 data"
  rect 0.6x0.5 smd: 1(-0.5,0) 2(0.5,0)
  body extent -0.55,-0.3 0.55,0.3, height 0.6
0603 [mm] "0603 from SM-752 data"
  rect 1x0.95 smd: 1(-0.8,0) 2(0.8,0)
  silkscreen extent -1.52,-0.69 1.52,0.69, body extent -0.87,-0.47 0.87,0.47, height 1
0603L [mm] "0603 from SM-752 data"
  rect 0.8x0.85 smd: 1(-0.7,0) 2(0.7,0)
  silkscreen extent -0.07,-0.33 0.07,0.33, body extent -0.87,-0.47 0.87,0.47, height 1
0805_HV [mil] "0805 with 30mil clearance between pads"
  rect 50x63 smd: 1(-40,0) 2(40,0)
  silkscreen extent -74,-40 74,40, body extent -43,-29 43,29, height 57
1206_190 [mm] "1206_190"
  rect 1.1x1.6 smd: 1(-1.7,0) 2(1.7,0)
  silkscreen extent -0.9,-1 0.9,1, body extent -1.75,-0.95 1.75,0.95, height 1.9
1210_270 [mm] "1210"
  rect 1.3x2.7 smd: 1(-1.45,0) 2(1.45,0)
  silkscreen extent -2.32,-1.57 2.32,1.57, body extent -1.7,-1.35 1.7,1.35, height 2.7
Abracon_ABLNO [mm] "SMD, 4-Leads, Body 8.7x14.3mm"
  rrect7% 2.5x1.5 smd: 1(-4.15,2.54) 2(-4.15,-2.54) 3(4.15,-2.54) 4(4.15,2.54)
  body extent -4.35,-7.15 4.35,7.15, height 5.5
AMPHENOL_901-144-8RFX [mm] "SMA Straight Jack, TH"
  round 2 hole 1.5: 1(0,0)
  round 2.2 hole 1.7: 2(-2.54,2.54) 3(-2.54,-2.54) 4(2.54,-2.54) 5(2.54,2.54)
  silkscreen extent -3.7,-3.7 3.7,3.7, body extent -3.7,-3.7 3.7,3.7, height 9.93
AssemblyNote [mil] "Assembly Note"
AssemblyNoteLabel [mil] "Assembly Note for PCB Labels"
CE_Mark_5mm [mil] "Minimum text height for CE Mark"
  silkscreen extent -138,-98 138,98
CONN_USB-Mini-B-1734035-2 [mm] "Tyco Connectivity recommended land pattern"
  rect 0.5x2.3 smd: 1(-1.6,2.6) 2(-0.8,2.6) 3(0,2.6) 4(0.8,2.6) 5(1.6,2.6)
  rect 2x2.5 smd: 6(4.45,2.5) 7(4.45,-3) 8(-4.45,-3) 9(-4.45,2.5)
  round 0.9 hole 0.9 unplated: 10(2.2,0) 11(-2.2,0)
  silkscreen extent -5,-5 4.9,4.19, body extent -4.95,-5.9 4.95,3.3, height 4.1
DBV0005A_L [mm] "SOT23, 5-Leads, Body 2.9x1.6mm, Pitch 0.95mm, Lead Span 2.8mm, IPC High Density"
  rrect18% 0.8x0.55 smd: 1(-1.275,0.95) 2(-1.275,0) 3(-1.275,-0.95) 4(1.275,-0.95) 5(1.275,0.95)
  silkscreen extent -0.35,-1.55 0.35,1.55, body extent -1.42,-1.46 1.42,1.46, height 1.09
DBV0005A_N [mm] "SOT23, 5-Leads, Body 2.9x1.6mm, Pitch 0.95mm, Lead Span 2.8mm, IPC Medium Density"
  rrect17% 1x0.6 smd: 1(-1.375,0.95) 2(-1.375,0) 3(-1.375,-0.95) 4(1.375,-0.95) 5(1.375,0.95)
  silkscreen extent -0.25,-1.55 0.25,1.55, body extent -1.42,-1.46 1.42,1.46, height 1.09
DBV0006A_N [mm] "SOT23, 6-Leads, Body 2.9x1.6mm, Pitch 0.95mm, Lead Span 2.8mm, IPC Medium Density"
  rrect17% 1x0.6 smd: 1(-1.375,0.95) 2(-1.375,0) 3(-1.375,-0.95) 4(1.375,-0.95) 5(1.375,0) 6(1.375,0.95)
  silkscreen extent -1.68,-1.55 0.5,1.55, body extent -1.42,-1.46 1.42,1.46, height 1.12
DCK0003A_N [mm] "SOT23, 3-Leads, Body 2.0x1.25mm, Pitch 0.65mm, Lead Span 2.1mm, IPC Medium Density"
  rrect25% 0.85x0.4 smd: 1(-1.125,0.65) 2(-1.125,-0.65) 3(1.125,0)
  silkscreen extent -1.02,-1.1 0.7,1.52, body extent -1.06,-1 1.06,1, height 1.1
DCK0005A_N [mm] "SOT353, 5-Leads, Body 2x1.3mm, Pitch 0.65mm, Lead Span 2.1mm, IPC Medium Density"
  rrect25% 0.85x0.4 smd: 1(-1.125,0.65) 2(-1.125,0) 3(-1.125,-0.65) 4(1.125,-0.65) 5(1.125,0.65)
  silkscreen extent -1.48,-1.02 0.55,1.1, body extent -1.14,-1 1.14,1, height 0.95
DGK0008A_L [mm] "TSOP, 8-Leads, Body 3x3mm, Pitch 0.65mm, IPC High Density"
  oval 1.15x0.45 smd: 1(-2.125,0.975) 2(-2.125,0.325) 3(-2.125,-0.325) 4(-2.125,-0.975) 5(2.125,-0.975) 6(2.125,-0.325) 7(2.125,0.325) 8(2.125,0.975)
  silkscreen extent -2.58,-1.55 0.95,1.55, body extent -2.45,-1.5 2.45,1.5, height 0.96
DGK0008A_N [mm] "TSOP, 8-Leads, Body 3x3mm, Pitch 0.65mm, IPC Medium Density"
  oval 1.35x0.45 smd: 1(-2.225,0.975) 2(-2.225,0.325) 3(-2.225,-0.325) 4(-2.225,-0.975) 5(2.225,-0.975) 6(2.225,-0.325) 7(2.225,0.325) 8(2.225,0.975)
  silkscreen extent -2.75,-1.55 0.95,1.55, body extent -2.45,-1.5 2.45,1.5, height 0.96
DGS0010A_L [mm] "TSSOP, 10-Leads, Body 3x3mm, Pitch 0.5mm, IPC High Density"
  oval 1.15x0.25 smd: 1(-2.125,1) 2(-2.125,0.5) 3(-2.125,0) 4(-2.125,-0.5) 5(-2.125,-1) 6(2.125,-1) 7(2.125,-0.5) 8(2.125,0) 9(2.125,0.5) 10(2.125,1)
  silkscreen extent -2.65,-1.55 0.9,1.55, body extent -2.45,-1.5 2.45,1.5, height 0.96
DRB0008A [mm] "VSON-8"
  rrect32% 0.6x0.31 smd: 1(-1.4,0.975) 2(-1.4,0.325) 3(-1.4,-0.325) 4(-1.4,-0.975) 5(1.4,-0.975) 6(1.4,-0.325) 7(1.4,0.325) 8(1.4,0.975)
  rrect7% 1.5x1.75 smd paste-0.75: 9(0,0)
  L1_Top Layer region: -0.7,-0.875 -0.49,-0.875 -0.471,-0.879 -0.455,-0.89 -0.444,-0.906 -0.44,-0.925 -0.44,-0.925 -0.44,-1.65 -0.436,-1.669 -0.425,-1.685 -0.409,-1.696 -0.39,-1.7 -0.39,-1.7 -0.26,-1.7 -0.241,-1.696 -0.225,-1.685 -0.214,-1.669 -0.21,-1.65 -0.21,-1.65 -0.21,-0.925 -0.206,-0.906 -0.195,-0.89 -0.179,-0.879 -0.16,-0.875 -0.16,-0.875 0.16,-0.875 0.179,-0.879 0.195,-0.89 0.206,-0.906 0.21,-0.925 0.21,-0.925 0.21,-1.65 0.21,-1.65 0.214,-1.669 0.225,-1.685 0.241,-1.696 0.26,-1.7 0.26,-1.7 0.39,-1.7 0.409,-1.696 0.425,-1.685 0.436,-1.669 0.44,-1.65 0.44,-1.65 0.44,-0.925 0.444,-0.906 0.455,-0.89 0.471,-0.879 0.49,-0.875 0.49,-0.875 0.7,-0.875 0.719,-0.871 0.735,-0.86 0.746,-0.844 0.75,-0.825 0.75,-0.825 0.75,0.825 0.746,0.844 0.735,0.86 0.719,0.871 0.7,0.875 0.7,0.875 0.49,0.875 0.471,0.879 0.455,0.89 0.444,0.906 0.44,0.925 0.44,0.925 0.44,1.65 0.436,1.669 0.425,1.685 0.409,1.696 0.39,1.7 0.39,1.7 0.26,1.7 0.241,1.696 0.225,1.685 0.214,1.669 0.21,1.65 0.21,1.65 0.21,1.65 0.21,0.925 0.206,0.906 0.195,0.89 0.179,0.879 0.16,0.875 0.16,0.875 -0.16,0.875 -0.179,0.879 -0.195,0.89 -0.206,0.906 -0.21,0.925 -0.21,0.925 -0.21,1.65 -0.214,1.669 -0.225,1.685 -0.241,1.696 -0.26,1.7 -0.26,1.7 -0.39,1.7 -0.409,1.696 -0.425,1.685 -0.436,1.669 -0.44,1.65 -0.44,1.65 -0.44,0.925 -0.444,0.906 -0.455,0.89 -0.471,0.879 -0.49,0.875 -0.49,0.875 -0.7,0.875 -0.719,0.871 -0.735,0.86 -0.746,0.844 -0.75,0.825 -0.75,0.825 -0.75,-0.825 -0.746,-0.844 -0.735,-0.86 -0.719,-0.871 -0.7,-0.875
  silkscreen extent -1.73,-1.73 1.73,1.73, body extent -1.5,-1.5 1.5,1.5, height 0.77
FCC_disclaimer [mil]
Fiducial10-20#1 [mm]
  round 1 smd mask+0.5: 1(0,0)
  L1_Top Layer keep-out circle w1.178: c0,0 r0.5
Fiducial10-20#2 [mm]
  round 1 smd far side mask+0.5: 1(0,0)
  L1_Top Layer keep-out circle w1.178: c0,0 r0.5
FP-ADT1-6T+_SMD6-MFG [mil]
  rrect6% 65x100 smd paste+0 mask+0: 1(-100,-100) 2(0,-100) 3(100,-100) 4(100,100) 5(0,100) 6(-100,100)
  silkscreen extent -158,-184 158,113, body extent -161,-154 161,154, height 10
FP-CVHD-957-10.000_SMT_XTAL_14MM2_9MM14-MFG [mm]
  rrect8% 1.27x2.28 smd paste+0 mask+0: 1(-2.54,-3.555) 2(0,-3.555) 3(2.54,-3.555) 4(2.54,3.555) 5(0,3.555) 6(-2.54,3.555)
  silkscreen extent -7.1,-5.57 7.1,4.57, body extent -7.1,-4.57 7.1,4.57, height 5.3
FP-ECS-100-12-33-AGN-TR_XTAL_SMD_3MM2_2MM5-MFG [mm]
  rrect9% 1.3x1.1 smd paste+0 mask+0: 1(-1.15,-0.9) 2(1.15,-0.9) 3(1.15,0.9) 4(-1.15,0.9)
  silkscreen extent -2.52,-1.3 0.13,1.3, body extent -1.9,-1.55 1.9,1.55, height 0.25
IND_LQG15H [mm] "MuRata"
  rect 0.55x0.6 smd: 1(-0.475,0) 2(0.475,0)
  silkscreen extent -1.3,-0.3 -0.95,0.3, body extent -0.52,-0.27 0.52,0.27, height 0.55
Johnson_142-0701-801#1 [mil] "Johnson Components recommended land pattern"
  rect 90x200 smd: 1(0,0)
  rect 95x200 smd: 2(-172.5,0) 3(172.5,0)
  round 38 hole 18 mask+1.97: 2(-172.5,-135) 3(172.5,-135)
  rect 95x200 smd far side: 4(-172.5,0) 5(172.5,0)
  L1_Top Layer lines w18: 172.5,0 172.5,-135 ; -172.5,0 -172.5,-135
  L6_Bottom Layer lines w18: 172.5,0 172.5,-135 ; -172.5,0 -172.5,-135
  silkscreen extent -235,-170 235,100, body extent -190,-92 190,480, height 165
